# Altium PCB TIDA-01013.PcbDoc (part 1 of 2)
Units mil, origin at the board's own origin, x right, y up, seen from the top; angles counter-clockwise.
Board outline 2500 x 2300 mil, 4 copper layers (Top Layer, Layer 2 -GND, Layer 3 - PWR, Bottom Layer), stack 59.034 mil thick; 218 components, 101 nets, 532 pads, 275 vias.
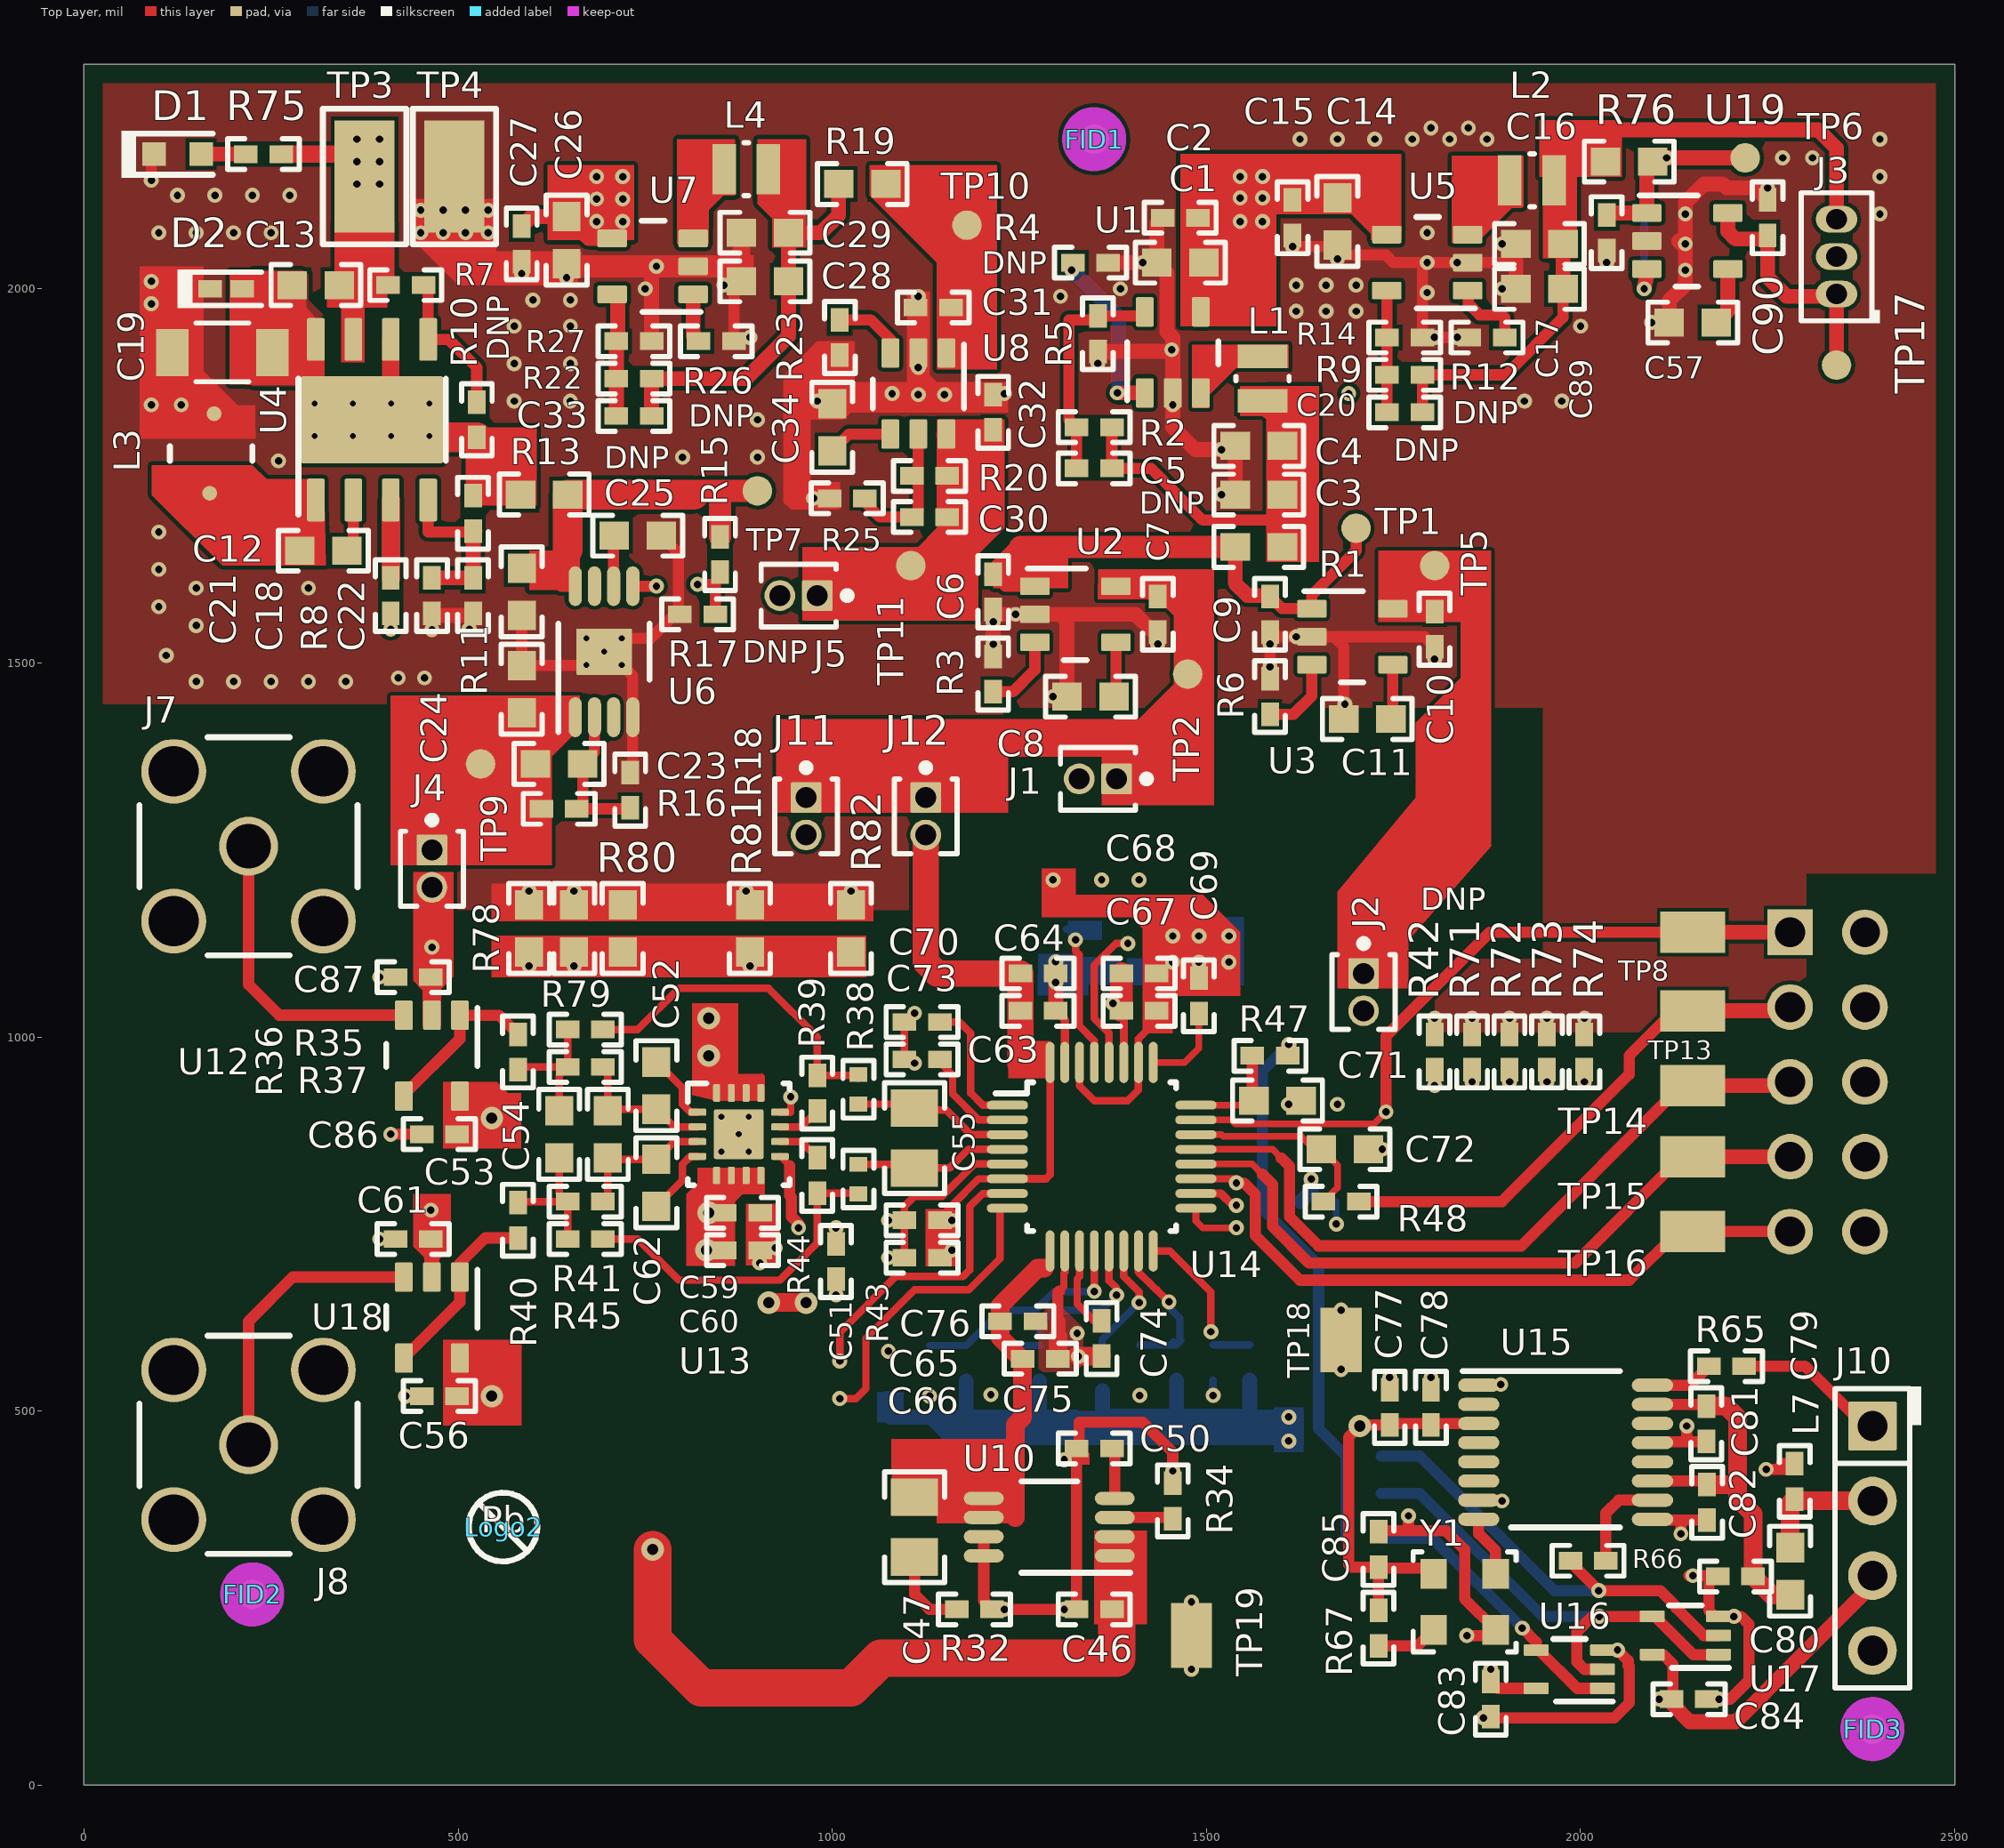
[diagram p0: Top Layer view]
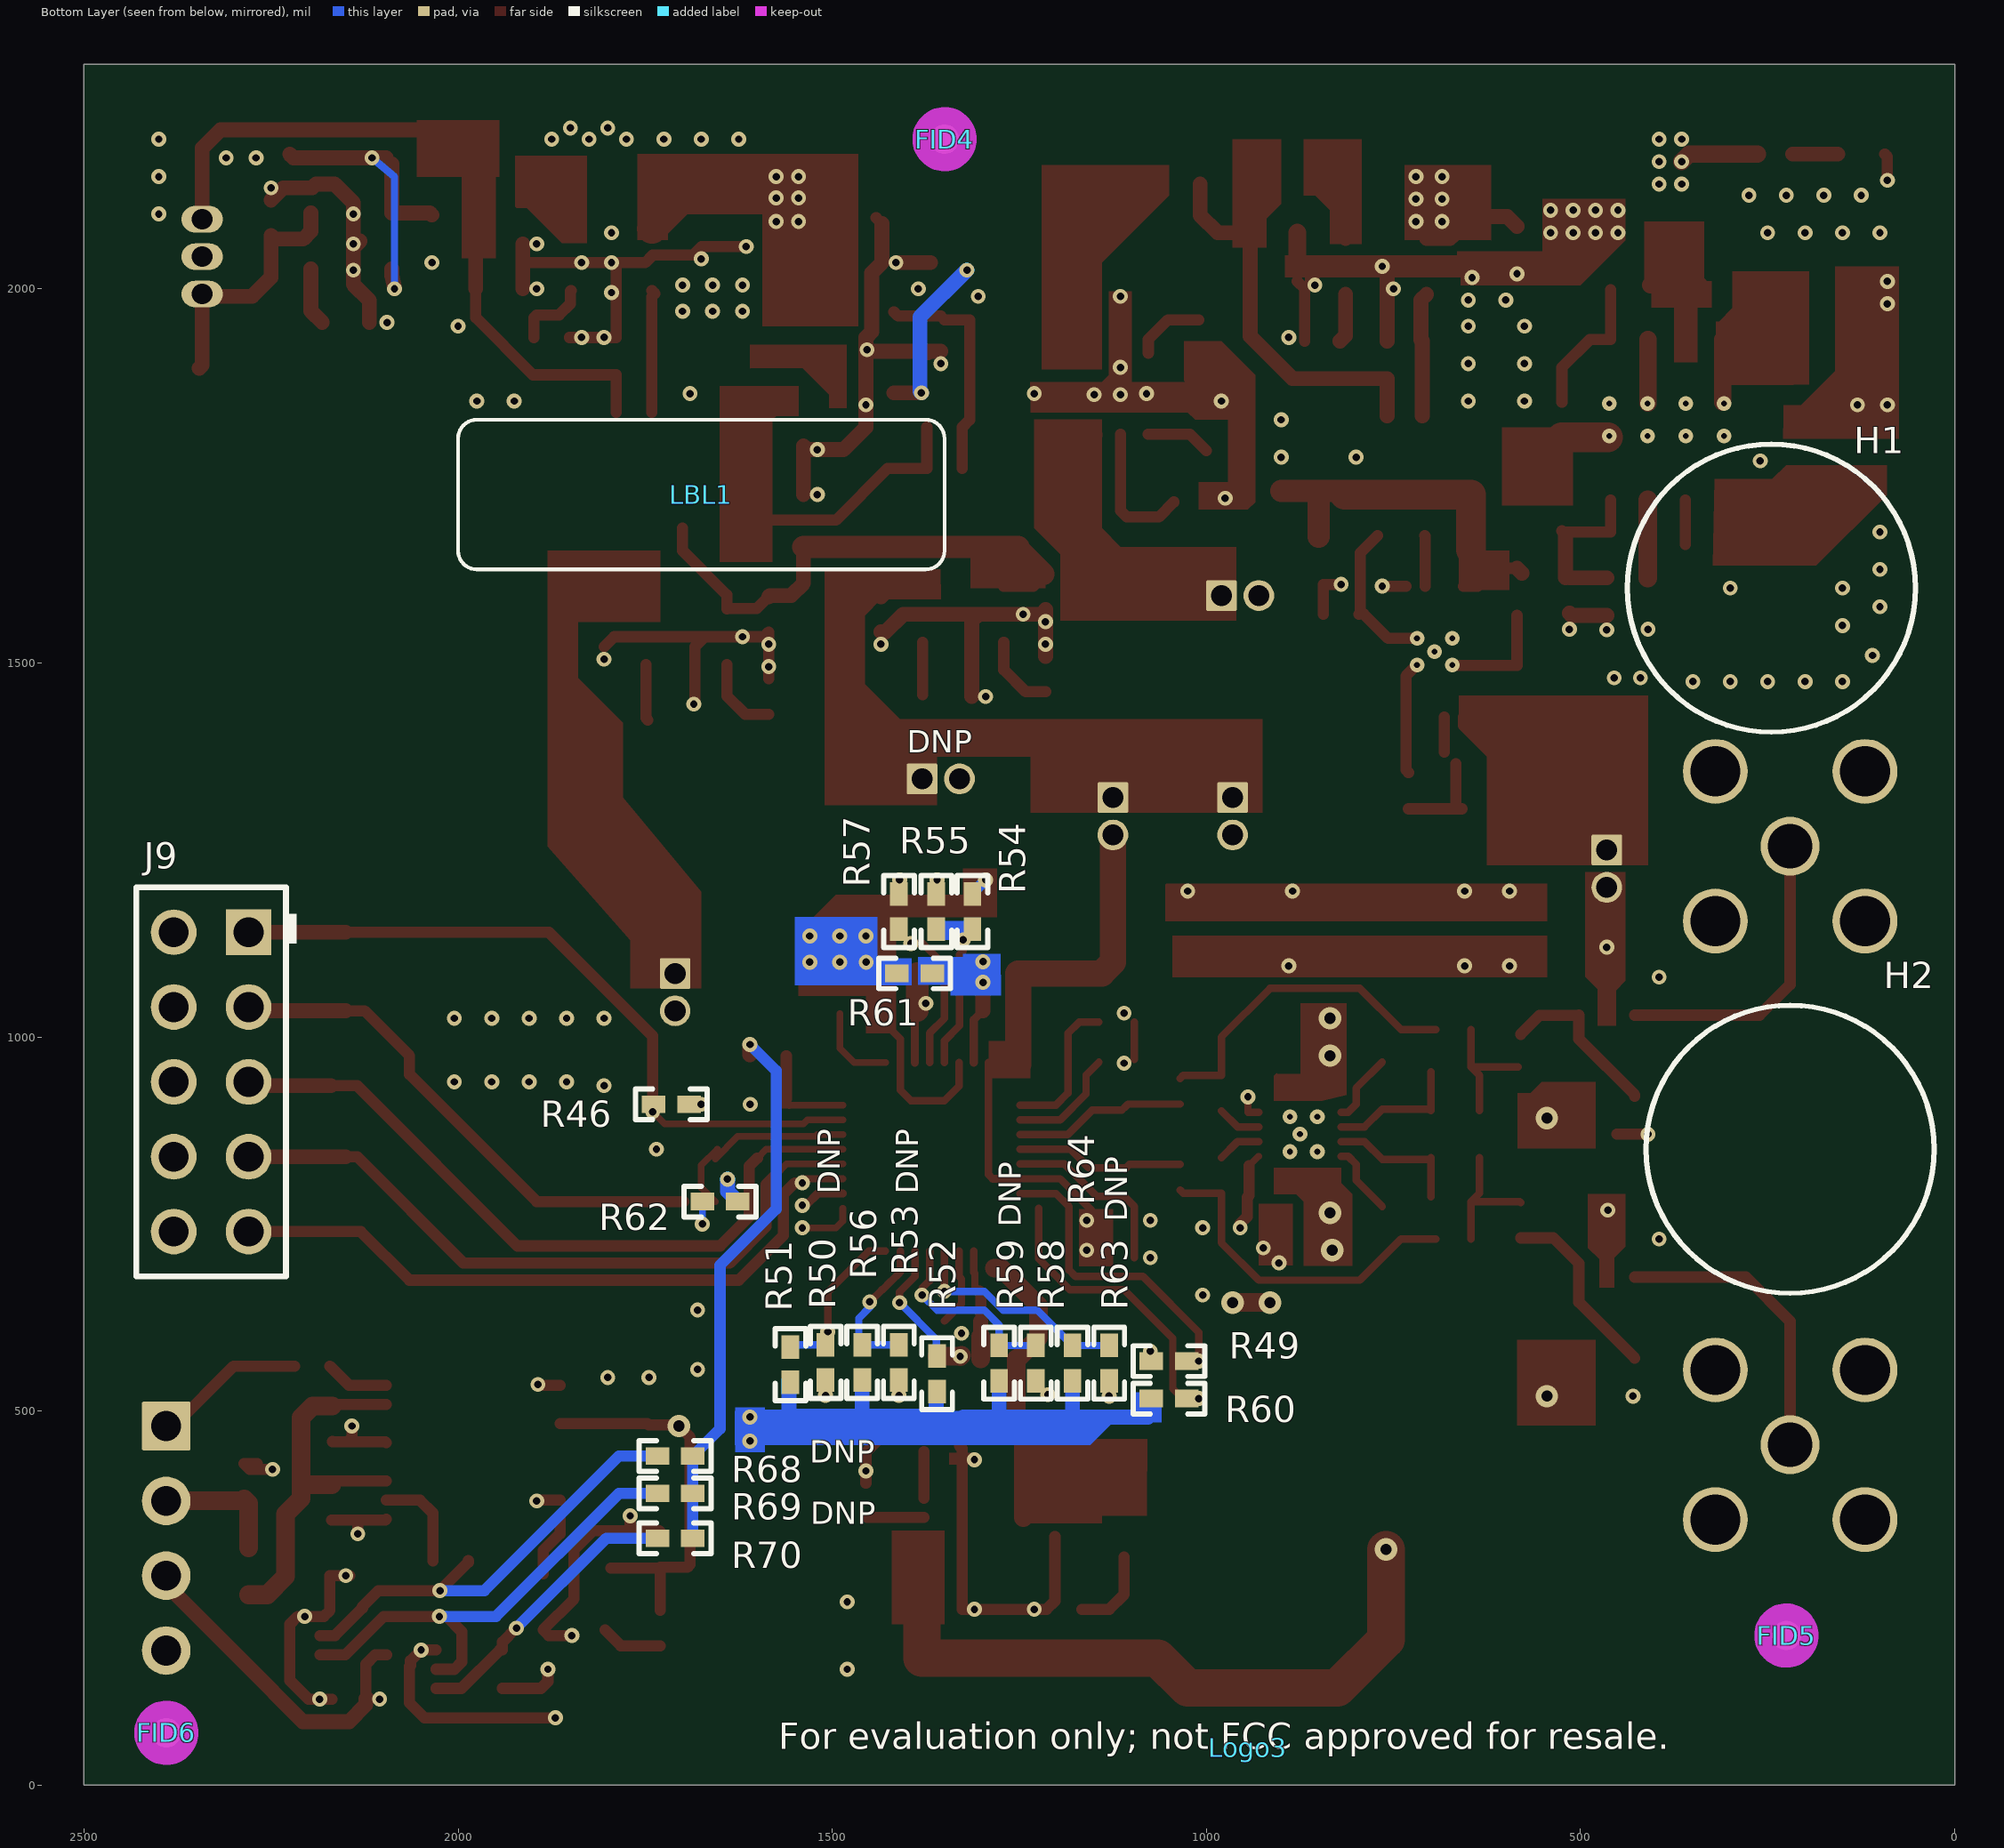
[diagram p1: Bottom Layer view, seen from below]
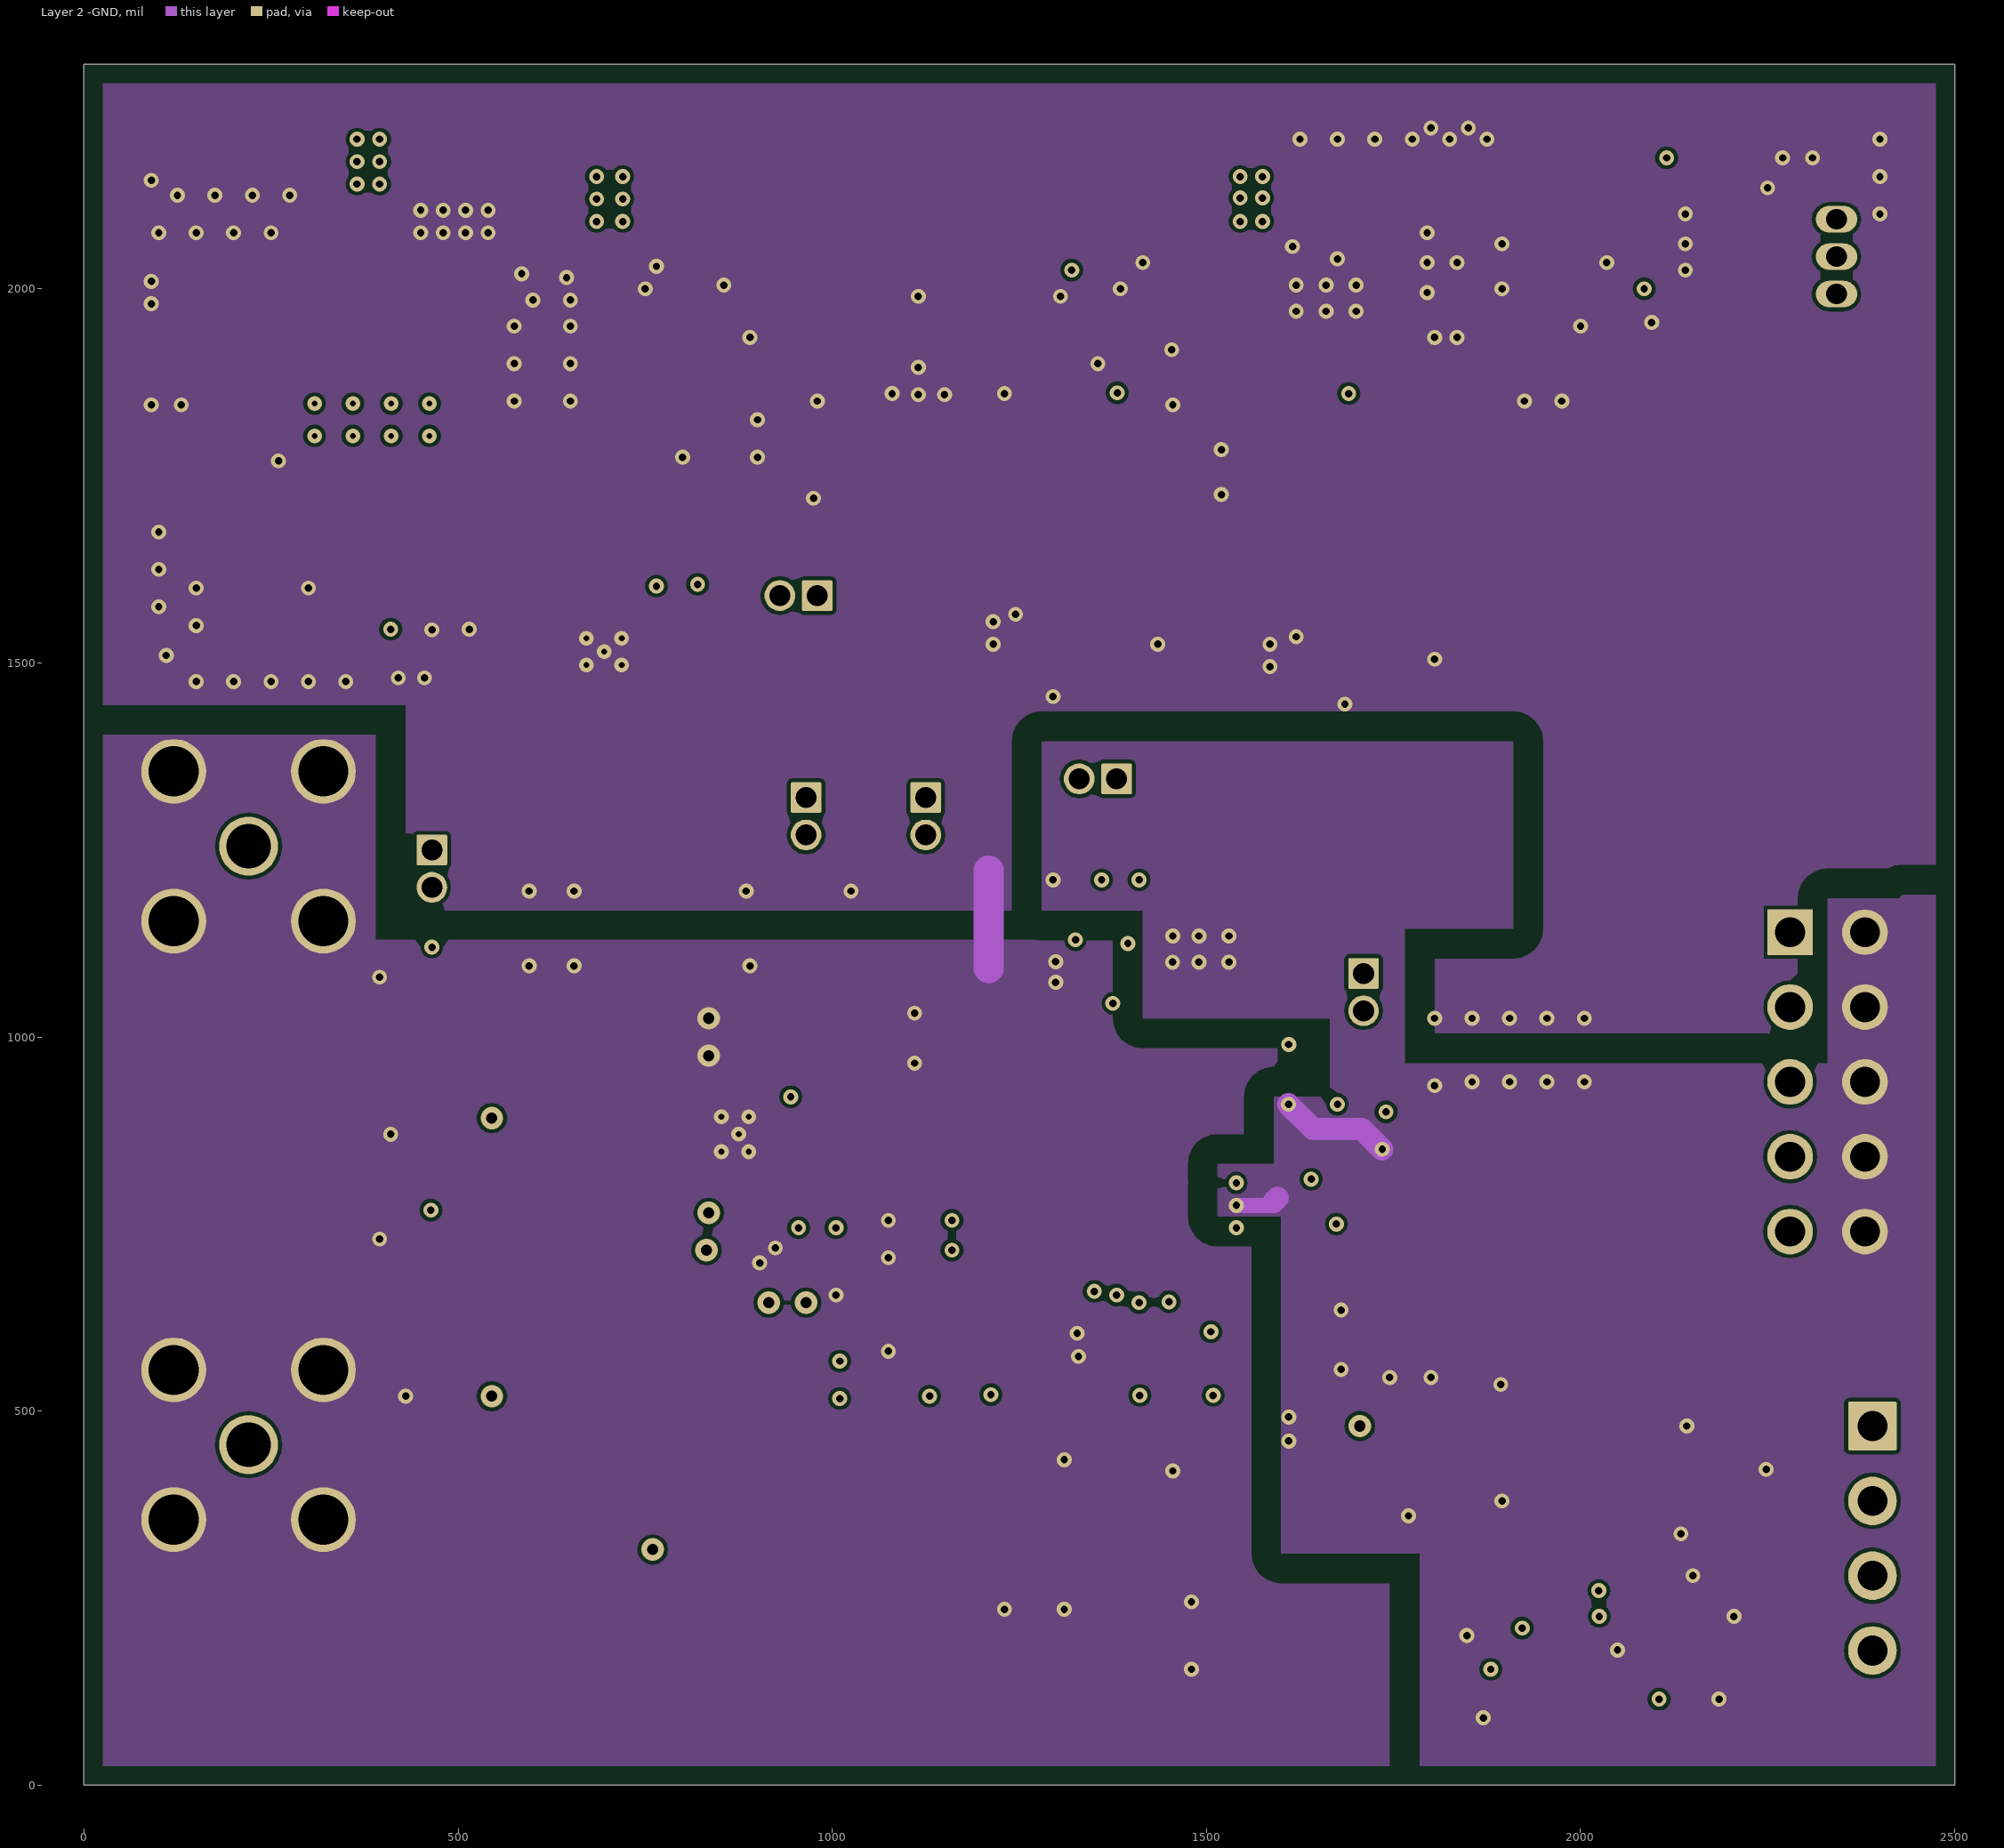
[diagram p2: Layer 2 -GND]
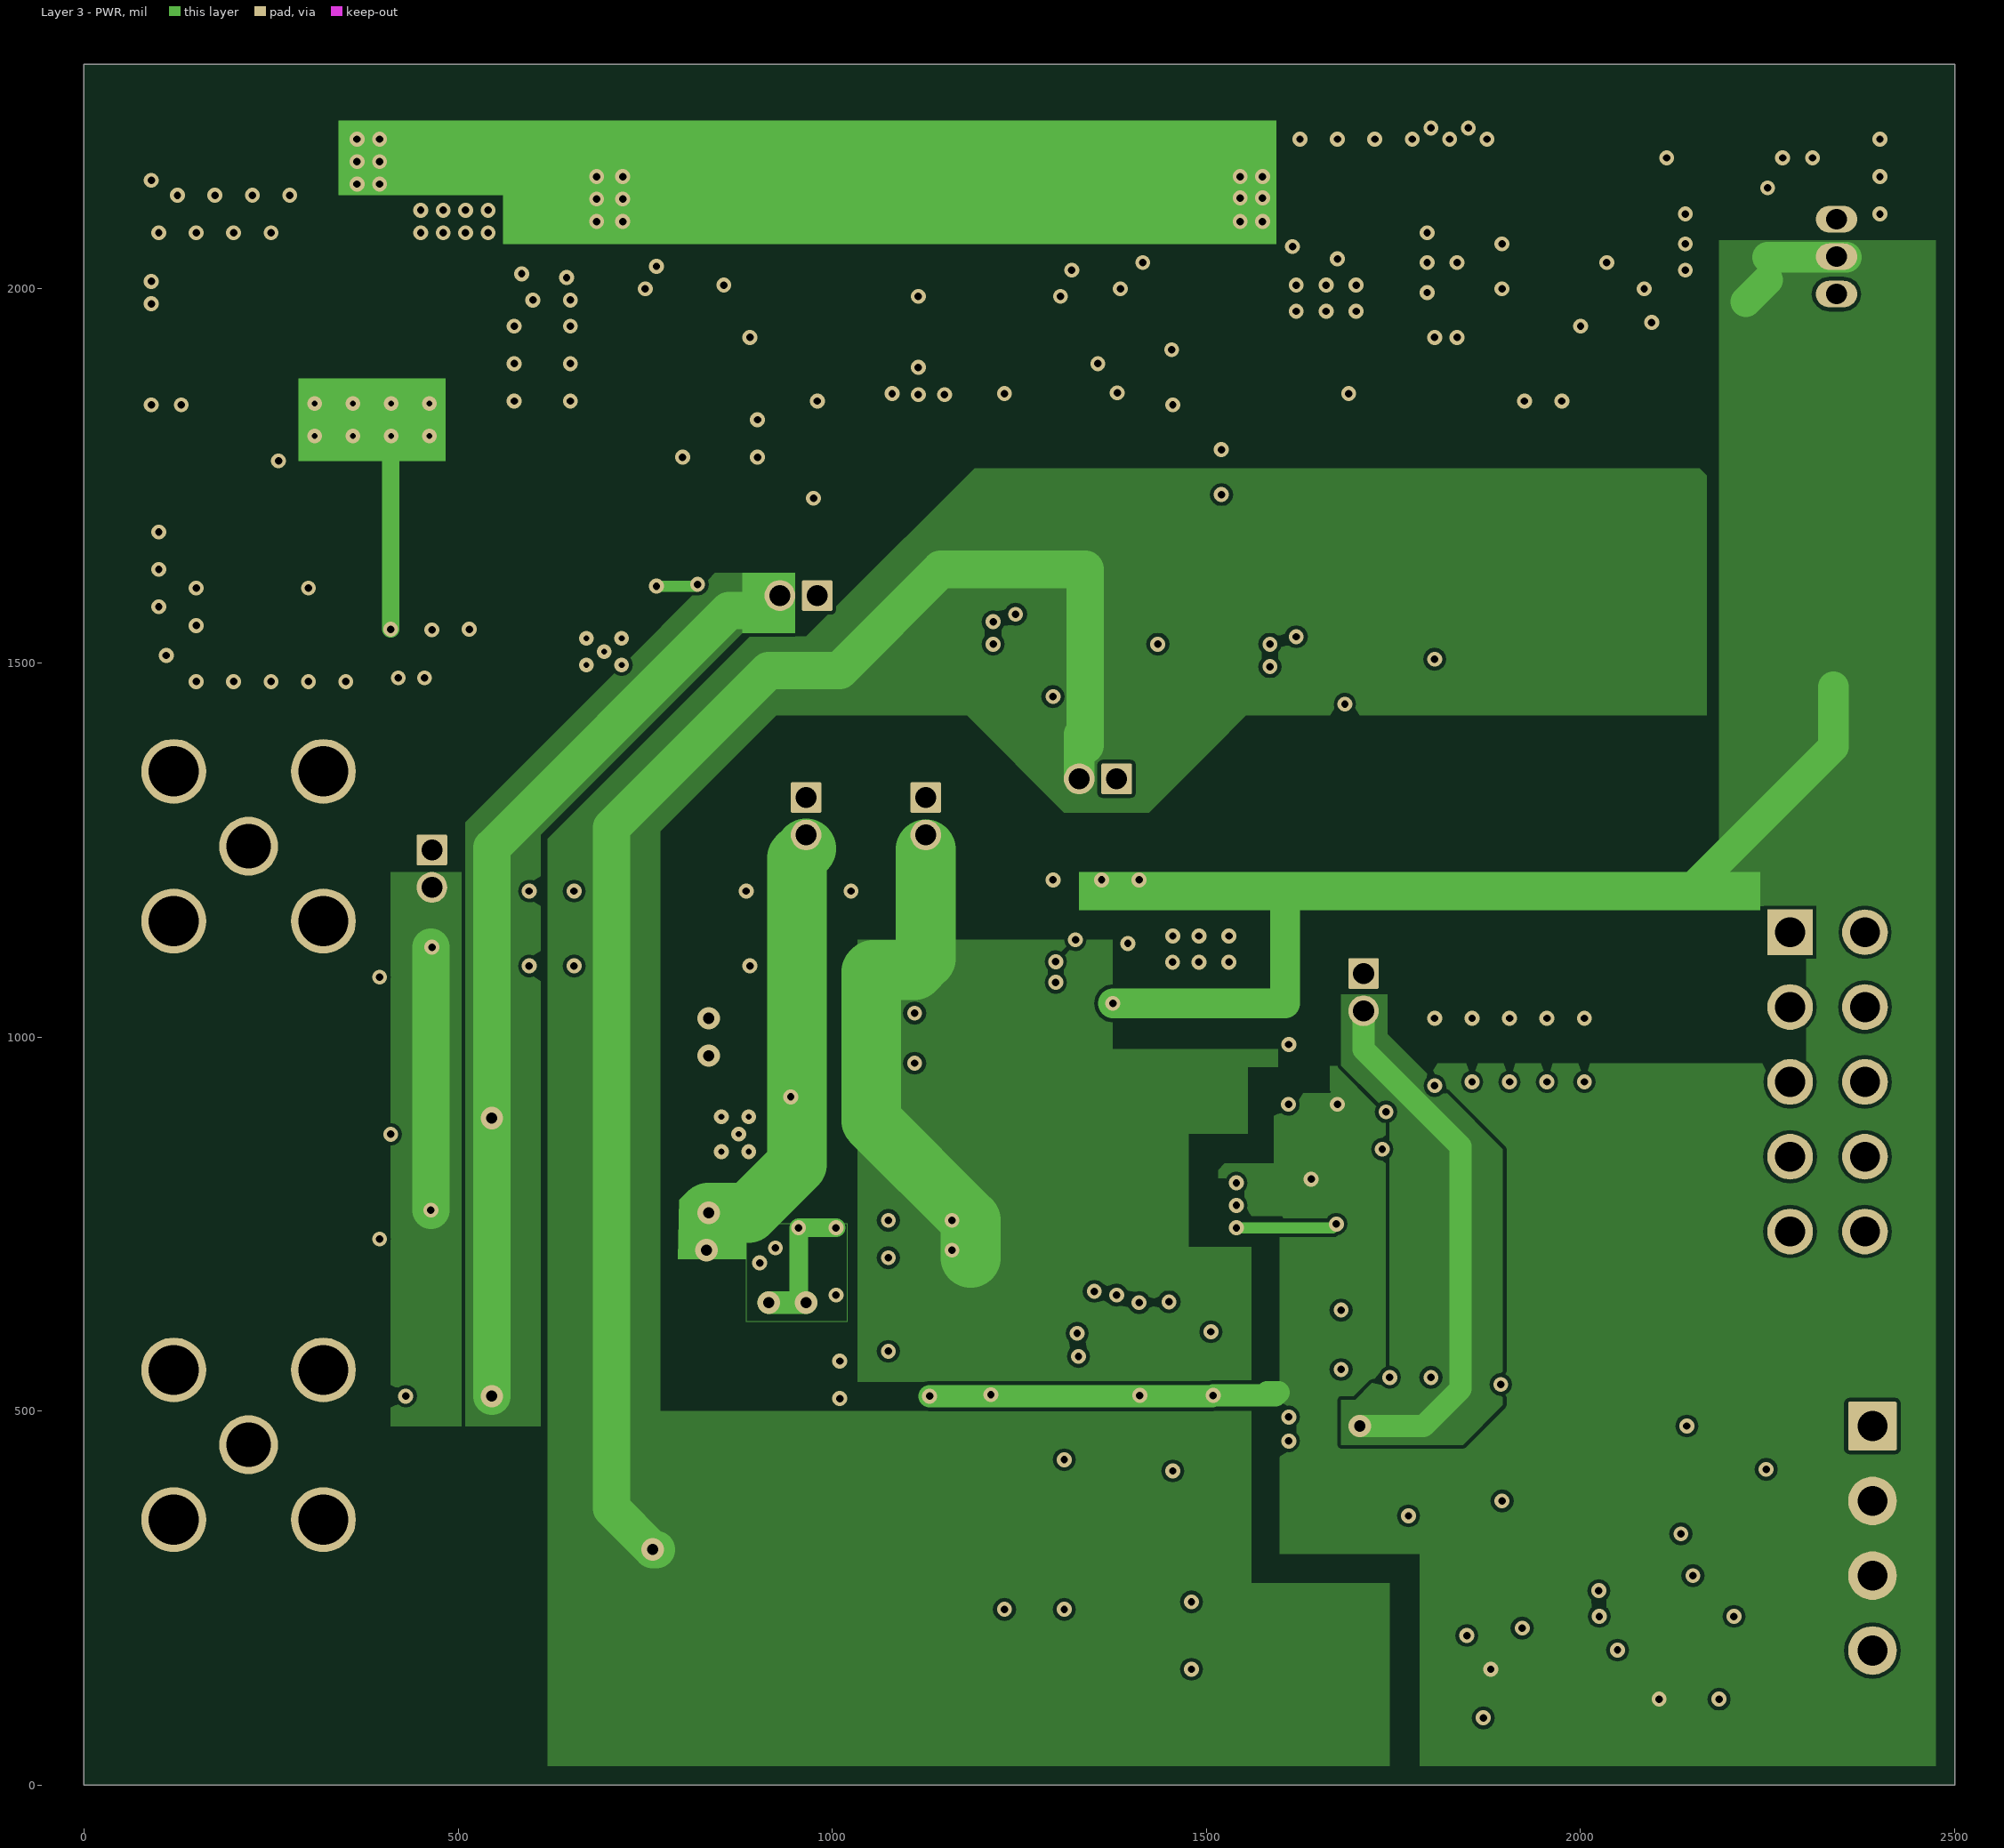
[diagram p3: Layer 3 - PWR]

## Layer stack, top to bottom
Top Solder: solder mask 0.4, Solder Resist, Dk 3.5
Top Layer: signal copper 1.4
Dielectric 1: prepreg 5.2, 370HR, Dk 4.2
Layer 2 -GND: signal copper 1.417
Dielectric 2: core 43, 370HR, Dk 4.2
Layer 3 - PWR: signal copper 1.417
Dielectric 3: prepreg 5.2, 370HR, Dk 4.2
Bottom Layer: signal copper 1.4
Bottom Solder: solder mask 0.4, Solder Resist, Dk 3.5

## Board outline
0,0 0,2300 2500,2300 2500,0

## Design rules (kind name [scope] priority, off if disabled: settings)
AcuteAngle [All] p1: minimum=4.50000000000000E+0001 checktracksonly=FALSE
AssemblyTestPointUsage [All] p1: valid=2
BoardOutlineClearance BoardOutlineClearance_MountingHoles [OnCopper and InComponentClass('Mounting Holes')] p1: gap=40
BoardOutlineClearance BoardOutlineClearance_Poly [OnCopper and IsPoly] p2: gap=25
BoardOutlineClearance [OnCopper and Not InComponentClass('Logo') and not InComponentClass('FiducialMark') and not InRegion(1000,500,4000,800) and not InPoly] p3: gap=75
Clearance Clearance_Keepouts [((IsTrack Or IsArc) And Not InPoly) And IsFree and IsKeepOut vs ((IsTrack Or IsArc) And Not InPoly) And IsFree and IsKeepOut] p1: gap=0
Clearance "Clearance_Poly_AGND TO DGND" [(InPolygon AND InNet('AGND')) vs (InPolygon AND InNet('DGND'))] p2: gap=40
Clearance Clearance_Poly [InPolygon] p3: gap=5
Clearance [All] p4: gap=7.87
ComponentClearance ComponentClearance_MountingHoles_FiducialMarks [InComponentClass('Mounting Holes') vs InComponentClass('FiducialMark')] p1: gap=50 collisioncheckmode=3 verticalgap=10 showdistances=FALSE
ComponentClearance ComponentClearance_Shunt [InComponentClass('Header') vs InComponentClass('Shunt')] p2: gap=0 collisioncheckmode=3 verticalgap=0 showdistances=FALSE
ComponentClearance ComponentClearance_Logo [InComponentClass('Logo')] p3: gap=10 collisioncheckmode=3 verticalgap=10 showdistances=FALSE
ComponentClearance ComponentClearance_ScrewToNut [(HasFootprint('NY PMS 440 0025 PH')) vs (HasFootprint('Keystone_1902C'))] p4: gap=5 collisioncheckmode=3 verticalgap=10 showdistances=FALSE
ComponentClearance ComponentClearance_MountingHoles [InComponentClass('Mounting Holes')] p5: gap=250 collisioncheckmode=3 verticalgap=100000 showdistances=FALSE
ComponentClearance ComponentClearance_SmallPassives [HasFootprint('0201*') or HasFootprint('0402*') or HasFootprint('0508') or HasFootprint('0603*') or HasFootprint('0612') or HasFootprint('0805*') or HasFootprint('0815*') or HasFootprint('0830*') or HasFootprint('1206*') or HasFootprint('1210*') or HasFootprint('1808*') or HasFootprint('1812*') or HasFootprint('1825*') or HasFootprint('2010*') or HasFootprint('2220*') or HasFootprint('2225*') or HasFootprint('2512*') or HasFootprint('2728*') or HasFootprint('3518*') vs HasFootprint('0201*') or HasFootprint('0402*') or HasFootprint('0508') or HasFootprint('0603*') or HasFootprint('0612') or HasFootprint('0805*') or HasFootprint('0815*') or HasFootprint('0830*') or HasFootprint('1206*') or HasFootprint('1210*') or HasFootprint('1808*') or HasFootprint('1812*') or HasFootprint('1825*') or HasFootprint('2010*') or HasFootprint('2220*') or HasFootprint('2225*') or HasFootprint('2512*') or HasFootprint('2728*') or HasFootprint('3518*')] p6: gap=14.96 collisioncheckmode=3 verticalgap=10 showdistances=FALSE
ComponentClearance ComponentClearance_THtoSMT [IsThruComponent vs IsSMTComponent] p7: gap=10 collisioncheckmode=3 verticalgap=30 showdistances=FALSE
ComponentClearance ComponentClearance_THtoTH [IsThruComponent vs IsThruComponent] p8: gap=30 collisioncheckmode=3 verticalgap=30 showdistances=FALSE
ComponentClearance [All] p9: gap=30 collisioncheckmode=3 verticalgap=10 showdistances=FALSE
DiffPairsRouting [All] p1: maxlimit=100 minlimit=10 mostfreqgap=10 toplayer_minwidth=15 toplayer_maxwidth=15 toplayer_prefwidth=15 midlayer1_minwidth=15 midlayer1_maxwidth=15 midlayer1_prefwidth=15 midlayer2_minwidth=15 midlayer2_maxwidth=15 midlayer2_prefwidth=15 bottomlayer_minwidth=15 bottomlayer_maxwidth=15 bottomlayer_prefwidth=15 maxuncoupledlength=1000
FabricationTestPointUsage TestPointUsage [All] p1: valid=2 allowmultiple=FALSE
FabricationTestpoint Testpoint [All] p1: side=3 testpointundercomponent=TRUE minsize=40 maxsize=100 preferedsize=60 minholesize=0 maxholesize=40 preferedholesize=32 testpointgrid=1 allowsidetop=TRUE allowsidebottom=TRUE usegrid=TRUE gridtolerance=0.01
FanoutControl Fanout_LCC [IsLCC] p1: bgadir=Out bgaviamode=Centered fanoutstyle=Auto fanoutdirection=Alternating viagrid=1 // Fanout_LCC (Default Rule)
FanoutControl Fanout_BGA [IsBGA] p2: bgadir=Out bgaviamode=Centered fanoutstyle=Auto fanoutdirection=Alternating viagrid=1 // Fanout_BGA (Default Rule)
FanoutControl Fanout_Default [All] p4: bgadir=Out bgaviamode=Centered fanoutstyle=Auto fanoutdirection=Alternating viagrid=1 // Fanout_Default (Default Rule)
FanoutControl Fanout_Small [(CompPinCount < 5)] p5: bgadir=Out bgaviamode=Centered fanoutstyle=Auto fanoutdirection=OutThenIn viagrid=1 // Fanout_Small (Default Rule)
HoleSize [All] p1: absolutevalues=TRUE maxlimit=251 minlimit=7.87 maxpercent=80.000 minpercent=20.000
MinimumAnnularRing MinimumAnnularRing_ThermalPadVias [IsVia and InAnyComponent] p1: minimumring=5.91
MinimumAnnularRing [All] p2: minimumring=3.5
MinimumSolderMaskSliver MinimumSolderMaskSliver_Logo [InComponentClass('Logo') vs InComponentClass('Logo')] p1: minsoldermaskwidth=0.7
MinimumSolderMaskSliver [All] p2: minsoldermaskwidth=3
PlaneConnect [All] p1: planeconnectstyle=Direct reliefexpansion=10 reliefentries=4 reliefconductorwidth=10 reliefairgap=10
PolygonConnect [All] p1: connectstyle=Direct reliefconductorwidth=10 reliefentries=4 polygonreliefangle="90 Angle" airgapwidth=10
RoutingVias ThermalPadVias [IsVia and InAnyComponent] p1: holewidth=7.87 width=19.68 viastyle="Through Hole" minholewidth=7.87 minwidth=19.68 maxholewidth=12.99 maxwidth=23.62
RoutingVias [All] p2: holewidth=16 width=34 viastyle="Through Hole" minholewidth=7.87 minwidth=20 maxholewidth=40 maxwidth=65
SilkToBoardRegionClearance [Not ((IsComment or IsDesignator) And (Hide <> 'False')) and not InRegion(1000,500,4000,800)] p1:
SilkToSilkClearance SilkToSilkClearance_Pb-FreeLogo [(HasFootprint('Pb-Free_Overlay_Medium') OR HasFootprint('Pb-Free_Overlay_Small')) vs (HasFootprint('Pb-Free_Overlay_Medium') OR HasFootprint('Pb-Free_Overlay_Small'))] p1: silktosilkclearance=0
SilkToSilkClearance [All] p2: silktosilkclearance=2
SilkToSolderMaskClearance SilkToComponentPadClearance [(IsPad or IsFill or IsRegion) and InAnycomponent] p1: minsilkscreentomaskgap=2 clearancetoexposedcopper=TRUE
SilkToSolderMaskClearance "Silk to Solder Mask Opening" [All] p2: minsilkscreentomaskgap=1 clearancetoexposedcopper=FALSE
SolderMaskExpansion [All] p1: expansion=1.97
Width [All] p1: maxlimit=100 minlimit=6 preferedwidth=10 checkconnectedcopper=TRUE
15 further rules are at their usual default settings.

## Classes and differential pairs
component class TIDA-01013_EVM_Hardware: !PCB FID1 FID2 FID3 FID4 FID5 FID6 LBL1 Logo2 Logo3 ZZ1 ZZ2 ZZ3 ZZ4
component class Label: LBL1
component class FiducialMark: FID1 FID2 FID3 FID4 FID5 FID6
component class AssemblyNote: ZZ1 ZZ2 ZZ3 ZZ4
component class Header: J1 J2 J3 J4 J5 J10 J11 J12 J?
component class LP_Front_End_ADC: C63 C64 C65 C66 "C66 DNP" C67 C68 C69 C70 C71 C72 C73 C74 C75 C76 J9 R42 R46 R47 R48 R49 R50 R51 R52 R53 R54 R55 R56 R57 R58 R59 R60 R61 R62 R63 R64 R71 R72 R73 R74 TP8 TP13 TP14 TP15 TP16 TP18 TP19 U14
component class LP_Front_End_AFE: 30 C46 C47 C50 C51 C52 C53 C54 C55 C56 C59 C60 C61 C62 C86 C87 J7 J8 R32 R34 R35 R36 R37 R38 R39 R40 R41 R43 R44 R45 U10 U12 U13 U18
component class LP_Front_End_ClockTree: C77 C78 C79 C80 C81 C82 C83 C84 C85 J10 L7 R65 R66 R67 R68 R69 R70 U15 U16 U17 Y1
component class LP_Front_End_PWR: C1 C2 C3 C4 C5 C6 C7 C8 C9 C10 C11 C12 C13 C14 C15 C16 C17 C18 C19 C20 C21 C22 C23 C24 C25 C26 C27 C28 C29 C30 C31 C32 C33 C34 C57 C89 C90 D1 D2 H1 H2 J1 J2 J3 J4 J5 J11 J12 J? L1 L2 L3 L4 R1 R2 R3 R4 R5 R6 R7 R8 R9 R10 R11 R12 R13 R14 R15 R16 R17 R18 R19 R20 R22 R23 R25 R26 R27 R75 R76 R78 R79 R80 R81 R82 TP1 TP2 TP3 TP4 TP5 TP6 TP7 TP9 TP10 TP11 TP17 U1 U2 U3 U4 U5 U6 U7 U8 U19

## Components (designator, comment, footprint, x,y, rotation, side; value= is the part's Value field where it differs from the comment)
C1 "C1608X5R1E106M080AC" 0603 1465,2035 r180 top
C2 "GRM155R61E104KA87D" 0402 1465,2095 r180 top
C3 "C1608X5R1E106M080AC" 0603 1570,1725 r180 top
C4 "C1608X5R1E106M080AC" 0603 1570,1790 r180 top
C5 "DNP" 0402 1350,1760 r180 top
C6 "GRM155R61E104KA87D" 0402 1215,1595 r270 top
C7 "GRM155R61E105KA12D" 0402 1435,1565 r270 top
C8 "GRM188R61H103KA01D" 0603 1345,1455 r180 top
C9 "GRM155R61E104KA87D" 0402 1585,1565 r270 top
C10 "GRM155R61E105KA12D" 0402 1805,1545 r270 top
C11 "GRM188R61H103KA01D" 0603 1715,1425 r180 top
C12 "GRM188R61E474KA12D" 0603 320,1650 r180 top
C13 "C1608X5R1E106M080AC" 0603 310,2005 r180 top
C14 "C1608X5R1E106M080AC" 0603 1675,2090 r270 top
C15 "GRM155R61E104KA87D" 0402 1615,2095 r270 top
C16 "C1608X5R1E106M080AC" 0603 1945,2060 r180 top
C17 "C1608X5R1E106M080AC" 0603 1945,2000 r180 top
C18 "GRM1555C1H910JA01D" 0402 465,1590 r90 top
C19 "C3216X5R1A686M160AC" 1206_190 185,1915 r0 top
C20 "DNP" 0402 1765,1835 r180 top
C21 "C1005X5R1E225K050BC" 0402 410,1590 r270 top
C22 "C1608X5R1E106M080AC" 0603 585,1595 r270 top
C23 "GRM188R61H103KA01D" 0603 635,1365 r0 top
C24 "C1608X5R1E106M080AC" 0603 585,1465 r90 top
C25 "GRM188R61H103KA01D" 0603 740,1670 r0 top
C26 "C1608X5R1E106M080AC" 0603 645,2065 r270 top
C27 "GRM155R61E104KA87D" 0402 585,2060 r270 top
C28 "C1608X5R1E106M080AC" 0603 910,2010 r180 top
C29 "C1608X5R1E106M080AC" 0603 910,2075 r180 top
C30 "GRM1555C1H130JA01D" 0402 1130,1695 r180 top
C31 "GRM155R61E104KA87D" 0402 1135,1975 r180 top
C32 "GRM155R61E105KA12D" 0402 1215,1835 r90 top
C33 "DNP" 0402 735,1830 r180 top
C34 "GRM188R61H103KA01D" 0603 1000,1815 r90 top
C46 "CL05A106MP5NUNC" 0402 1350,235 r180 top
C47 "GRM21BR61A476ME15" 0805_HV 1110,345 r270 top
C50 "GRM155R61A105KE15D" 0402 1350,450 r180 top
C51 "C1005X5R1A224K050BC" 0402 1005,700 r270 top
C52 "GRM1885C2A271JA01D" 0603 765,935 r270 top
C53 "C1608C0G2A471J" 0603 635,870 r270 top
C54 "C1608C0G2A102J080AA" 0603 700,870 r270 top
C55 "GRM2165C2A162JA01D" 0805_HV 1110,865 r270 top
C56 "C1005X5R1A104K050BA" 0402 475,520 r0 top
C57 "GRM188R61H103KA01D" 0603 2150,1955 r180 top
C59 "C1005X5R1A104K050BA" 0402 880,765 r0 top
C60 "CL05A106MP5NUNC" 0402 880,715 r180 top
C61 "C1005X5R1A104K050BA" 0402 440,730 r0 top
C62 "GRM1885C2A271JA01D" 0603 765,805 r90 top
C63 "C1005X5R1A104K050BA" 0402 1275,1035 r180 top
C64 "CL05A106MP5NUNC" 0402 1275,1085 r0 top
C65 "C1005X5R1A104K050BA" 0402 1120,755 r0 top
C66 "CL05A106MP5NUNC" 0402 1120,705 r180 top
C67 "C1005X5R1A104K050BA" 0402 1410,1035 r180 top
C68 "CL05A106MP5NUNC" 0402 1410,1085 r0 top
C69 "GRM155R61A105KE15D" 0402 1490,1055 r90 top
C70 "GRM155R61A105KE15D" 0402 1120,1020 r0 top
C71 "06035A100JAT2A" 0603 1595,915 r0 top
C72 "GRM1885C2A100JA01D" 0603 1685,850 r0 top
C73 "GRM155R61A105KE15D" 0402 1120,970 r180 top
C74 "GRM155R61A105KE15D" 0402 1360,597 r270 top
C75 "GRM155R61A105KE15D" 0402 1278,570 r0 top
C76 "C1005X5R1A104K050BA" 0402 1248,620 r180 top
C77 "CL05A106MP5NUNC" 0402 1745,505 r90 top
C78 "C1005X5R1A104K050BA" 0402 1800,505 r270 top
C79 "CL05A106MP5NUNC" 0402 2286,406 r90 top
C80 "GRM155R61A105KE15D" 0402 2207,279 r180 top
C81 "C1005X5R1A104K050BA" 0402 2168,483 r90 top
C82 "C1005X5R1A104K050BA" 0402 2169,378 r90 top
C83 "C1005X5R1A104K050BA" 0402 1880,115 r270 top
C84 "C1005X5R1A104K050BA" 0402 2145,115 r0 top
C85 "C1005X5R1A104K050BA" 0402 1730,315 r270 top
C86 "C1005X5R1A104K050BA" 0402 475,870 r0 top
C87 "C1005X5R1A104K050BA" 0402 440,1080 r0 top
C89 "GRM155R61E104KA87D" 0402 2035,2075 r270 top
C90 "GRM155R61E105KA12D" 0402 2250,2095 r90 top
D1 "150060RS75000" WL-SMCW_RED 125,2180 r0 top
D2 "BAT41KFILM" SOD-523 190,2000 r0 top
FID1 "Fiducial" Fiducial10-20 1350,2200 r0 top
FID2 "Fiducial" Fiducial10-20 225,255 r0 top
FID3 "Fiducial" Fiducial10-20 2390,75 r0 top
FID4 "Fiducial" Fiducial10-20 1350,2200 r180 bottom
FID5 "Fiducial" Fiducial10-20 225,200 r180 bottom
FID6 "Fiducial" Fiducial10-20 2390,70 r180 bottom
H1 "SJ61A2" Bumpon_SJ61A2 245,1600 r90 bottom
H2 "SJ61A2" Bumpon_SJ61A2 220,850 r180 bottom
J1 "GRPB021VWVN-RC" Sullins_GRPB021VWVN-RC 1355,1345 r180 top
J2 "GRPB021VWVN-RC" Sullins_GRPB021VWVN-RC 1710,1060 r270 top
J3 "GRPB031VWVN-RC" Sullins_GRPB031VWVN-RC 2342,2043 r90 top
J4 "GRPB021VWVN-RC" Sullins_GRPB021VWVN-RC 465,1225 r270 top
J5 "GRPB021VWVN-RC" Sullins_GRPB021VWVN-RC 955,1590 r180 top
J7 "AINN" Amphenol_901-144-8RFX 220,1255 r0 top
J8 "AINP" Amphenol_901-144-8RFX 220,455 r0 top
J9 "PPTC052LFBN-RC" Sullins_xPxC052LFBN 2330,940 r270 bottom
J10 "TSW-104-07-G-S" TSW-104-07-G-S 2390,330 r270 top
J11 "GRPB021VWVN-RC" Sullins_GRPB021VWVN-RC 965,1295 r270 top
J12 "GRPB021VWVN-RC" Sullins_GRPB021VWVN-RC 1125,1295 r270 top
L1 "SRN2010TA-100M" SRN2010TA 1575,1880 r270 top
L2 "SRN2010TA-100M" SRN2010TA 1935,2145 r0 top
L3 "SRU2016-220Y" SRU2016 170,1780 r90 top
L4 "SRN2010TA-100M" SRN2010TA 885,2160 r0 top
L7 "HZ0603C601R-10" 0603 2280,286 r270 top
LBL1 "Size: 0.65\" x 0.20 \"" Label_650x200 1675,1725 r180 bottom
Logo2 "Pb-Free Symbol" Pb-Free_Overlay_Small 560,345 r0 top
Logo3 "FCC disclaimer" FCC_disclaimer 945,50 r180 bottom
R1 "CRCW06030000Z0EA" 0603 1570,1655 r180 top
R2 "CRCW0402100KFKED" 0402 1350,1815 r0 top
R3 "" 0402 1215,1485 r90 top
R4 "DNP" 0402 1345,2035 r0 top
R5 "CRCW040230K9FKED" 0402 1355,1940 r90 top
R6 "" 0402 1585,1455 r90 top
R7 "" 0402 430,2005 r0 top
R8 "CRCW040275K0FKED" 0402 520,1590 r270 top
R9 "CRCW0402105KFKED" 0402 1765,1885 r0 top
R10 "DNP" 0402 525,1825 r90 top
R11 "CRCW040217K4FKED" 0402 520,1700 r270 top
R12 "DNP" 0402 1875,1935 r180 top
R13 "CRCW06030000Z0EA" 0603 615,1725 r0 top
R14 "CRCW040239K2FKED" 0402 1765,1935 r180 top
R15 "" 0402 850,1645 r270 top
R16 "CRCW040236K0JNED" 0402 635,1305 r180 top
R17 "DNP" 0402 820,1565 r0 top
R18 "CRCW040210K5FKED" 0402 730,1330 r270 top
R19 "CRCW06030000Z0EA" 0603 1040,2140 r0 top
R20 "ERJ-2RKF9762X" 0402 1130,1750 r0 top
R22 "RC0402FR-07100KL" 0402 735,1880 r0 top
R23 "" 0402 1010,1935 r270 top
R25 "RC0402FR-0730K1L" 0402 1020,1720 r0 top
R26 "DNP" 0402 845,1930 r0 top
R27 "CRCW040217K8FKED" 0402 735,1930 r180 top
R32 "ERJ-2BQFR22X" 0402 1190,235 r180 top
R34 "CRCW0402120KFKED" 0402 1455,380 r270 top
R35 "ERA-2AEB102X" 0402 670,1010 r0 top
R36 "CRCW04023K40FKED" 0402 580,980 r270 top
R37 "ERJ-2RKF3300X" 0402 670,960 r0 top
R38 "CPF0402B10RE1" CPF0402 1035,930 r270 top
R39 "CRCW04024R99FKED" 0402 980,925 r90 top
R40 "CRCW04023K40FKED" 0402 580,755 r90 top
R41 "ERJ-2RKF3300X" 0402 670,780 r0 top
R42 "DNP" 0402 1805,980 r90 top
R43 "CPF0402B10RE1" CPF0402 1035,810 r90 top
R44 "CRCW04024R99FKED" 0402 980,815 r270 top
R45 "ERA-2AEB102X" 0402 670,730 r0 top
R46 "RMCF0402FT100K" 0402 1715,910 r0 bottom
R47 "CRCW040210R0FKED" 0402 1585,975 r0 top
R48 "CRCW04020000Z0ED" 0402 1680,780 r0 top
R49 "CRCW0402120KFKED" 0402 1050,566.79 r180 bottom
R50 "DNP" 0402 1509,565 r270 bottom
R51 "CRCW04020000Z0ED" 0402 1556,562 r90 bottom
R52 "CRCW04020000Z0ED" 0402 1360,550 r270 bottom
R53 "DNP" 0402 1411,565 r270 bottom
R54 "CRCW04020000Z0ED" 0402 1312.78,1167.66 r270 bottom
R55 "DNP" 0402 1360.96,1167.66 r90 bottom
R56 "CRCW04020000Z0ED" 0402 1460,565 r90 bottom
R57 "CRCW0402100KFKED" 0402 1410.96,1167.66 r90 bottom
R58 "CRCW04020000Z0ED" 0402 1228,564 r270 bottom
R59 "DNP" 0402 1277,564 r90 bottom
R60 "RK73H1ETTP1002F" 0402 1050,516.79 r0 bottom
R61 "DNP" 0402 1390,1085 r180 bottom
R62 "RMCF0402FT100K" 0402 1650,780 r180 bottom
R63 "DNP" 0402 1130,564 r270 bottom
R64 "CRCW04020000Z0ED" 0402 1179,564 r90 bottom
R65 "CRCW040243R2FKED" 0402 2195,560 r0 top
R66 "CRCW040243R2FKED" 0402 2010,300 r180 top
R67 "RMCF0402FT100K" 0402 1730,210 r90 top
R68 "DNP" 0402 1710,440 r0 bottom
R69 "DNP" 0402 1710,390 r0 bottom
R70 "" 0402 1710,330 r0 bottom
R71 "DNP" 0402 1855,980 r90 top
R72 "DNP" 0402 1905,980 r90 top
R73 "DNP" 0402 1955,980 r90 top
R74 "DNP" 0402 2005,980 r90 top
R75 "PCF0402-03-49K9BT1" 0402 240,2180 r0 top
R76 "CRCW06030000Z0EA" 0603 2065,2170 r0 top
R78 "DNP" 0603 595,1145 r90 top
R79 "DNP" 0603 655,1145 r90 top
R80 "DNP" 0603 720,1145 r90 top
R81 "DNP" 0603 890,1145 r90 top
R82 "DNP" 0603 1025,1145 r90 top
TP1 "TESTPOINT" TP_SM_1MM 1700,1680 r0 top
TP2 "TESTPOINT" TP_SM_1MM 1475,1485 r90 top
TP3 "TESTPOINT" Keystone_5019 375,2150 r90 top
TP4 "TESTPOINT" Keystone_5019 495,2150 r90 top
TP5 "TESTPOINT" TP_SM_1MM 1805,1630 r180 top
TP6 "TESTPOINT" TP_SM_1MM 2220,2175 r0 top
TP7 "TESTPOINT" TP_SM_1MM 900,1730 r0 top
TP8 "TESTPOINT" Harwin_S2751-46R 2150,1140 r180 top
TP9 "TESTPOINT" TP_SM_1MM 530,1365 r0 top
TP10 "TESTPOINT" TP_SM_1MM 1180,2085 r180 top
TP11 "TESTPOINT" TP_SM_1MM 1105,1630 r0 top
TP13 "TESTPOINT" Harwin_S2751-46R 2150,1035 r0 top
TP14 "TESTPOINT" Harwin_S2751-46R 2150,935 r0 top
TP15 "TESTPOINT" Harwin_S2751-46R 2150,840 r0 top
TP16 "TESTPOINT" Harwin_S2751-46R 2150,740 r180 top
TP17 "TESTPOINT" TP_SM_1MM 2342,1898 r90 top
TP18 "TESTPOINT" Harwin_S2751-46R 1680,595 r90 top
TP19 "TESTPOINT" Harwin_S2751-46R 1480,200 r90 top
U1 "TPS560200DBVR" DBV0005A_N 1455,1915 r90 top
U2 "TPS79133DBVR" DBV0005A_N 1325,1565 r0 top
U3 "TPS79133DBVR" DBV0005A_N 1695,1535 r0 top
U4 "LMR23610ADDAR" DDA0008E_N 385,1825 r90 top
U5 "TPS560200DBVR" DBV0005A_N 1795,2035 r180 top
U6 "TPS7A3001DGNR" DGN0008D_N 695,1515 r90 top
U7 "TPS560200DBVR" DBV0005A_N 760,2030 r180 top
U8 "TPS79101DBVR" DBV0006A_N 1115,1860 r270 top
U10 "REF6030IDGKR" DGK0008A_N 1290,345 r180 top
U12 "OPA191IDBVR" DBV0005A_N 465,975 r270 top
U13 "THS4551IRGTR" RGT0016C 875,870 r0 top
U14 "ADS127L01IPBSR" PBS0032A_N 1360,840 r0 top
U15 "LMK00804BPW" PW0016A_N 1980,445 r0 top
U16 "SN74AUP1G80DCKR" DCK0005A_N 1985,155 r180 top
U17 "SN74AUP1G80DCKR" DCK0005A_N 2140,200 r180 top
U18 "OPA191IDBVR" DBV0005A_N 465,625 r270 top
U19 "TPS73118DBVR" DBV0005A_N 2142.69,2064 r0 top
Y1 "ASEMB-16.000MHZ-XY-T" ABRACON_ASEMB 1845,245 r90 top
ZZ1 "This Assembly Note is for PCB labels only" AssemblyNoteLabel -150,4500 r0 top
ZZ2 "These assemblies are ESD sensitive, ESD precautions shall be observed." AssemblyNote -150,4300 r0 top
ZZ3 "These assemblies must be clean and free from flux and all contaminants. Use of no clean flux is not acceptable." AssemblyNote -150,4100 r0 top
ZZ4 "These assemblies must comply with workmanship standards IPC-A-610 Class 2, unless otherwise specified." AssemblyNote -150,3900 r0 top

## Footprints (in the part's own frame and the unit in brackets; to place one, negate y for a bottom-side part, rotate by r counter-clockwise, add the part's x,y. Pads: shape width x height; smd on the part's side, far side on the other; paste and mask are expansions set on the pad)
0402 [mm] "0402 from SM-752 data"
  rect 0.8x0.6 smd: 1(-0.6,0) 2(0.6,0)
  silkscreen extent -1.22,-0.52 1.22,0.52, body extent -0.55,-0.3 0.55,0.3, height 0.6
0603 [mm] "0603 from SM-752 data"
  rect 1x0.95 smd: 1(-0.8,0) 2(0.8,0)
  silkscreen extent -1.52,-0.69 1.52,0.69, body extent -0.87,-0.47 0.87,0.47, height 1
0805_HV [mil] "0805 with 30mil clearance between pads"
  rect 50x63 smd: 1(-40,0) 2(40,0)
  silkscreen extent -74,-40 74,40, body extent -43,-29 43,29, height 57
1206_190 [mm] "1206_190"
  rect 1.1x1.6 smd: 1(-1.7,0) 2(1.7,0)
  silkscreen extent -0.9,-1 0.9,1, body extent -1.75,-0.95 1.75,0.95, height 1.9
ABRACON_ASEMB [mm] "ASEMB Series Oscillator"
  rect 1x0.9 smd: 1(-0.95,1.05) 2(-0.95,-1.05) 3(0.95,-1.05) 4(0.95,1.05)
  silkscreen extent -1.7,-1.75 1.7,1.75, body extent -1.25,-1.6 1.25,1.6, height 0.95
Amphenol_901-144-8RFX [mm] "SMA Straight Jack, TH"
  round 2 hole 1.5: 1(0,0)
  round 2.2 hole 1.7: 2(-2.54,2.54) 3(-2.54,-2.54) 4(2.54,-2.54) 5(2.54,2.54)
  silkscreen extent -3.7,-3.7 3.7,3.7, body extent -3.7,-3.7 3.7,3.7, height 9.93
AssemblyNote [mil] "Assembly Note"
AssemblyNoteLabel [mil] "Assembly Note for PCB Labels"
Bumpon_SJ61A2 [mil] "3M Hemispherical Bumpon transparent"
  round 1 on Mech4: 0(0,0)
  silkscreen extent -192,-192 192,192, body extent -193,-192 193,192, height 250
CPF0402 [mm] "TE Connectivity"
  rect 0.5x0.6 smd: 1(-0.5,0) 2(0.5,0)
  silkscreen extent -0.97,-0.53 0.97,0.53, body extent -0.55,-0.27 0.55,0.27, height 0.35
DBV0005A_N [mm] "SOT23, 5-Leads, Body 2.9x1.6mm, Pitch 0.95mm, Lead Span 2.8mm, IPC Medium Density"
  rrect17% 1x0.6 smd: 1(-1.375,0.95) 2(-1.375,0) 3(-1.375,-0.95) 4(1.375,-0.95) 5(1.375,0.95)
  silkscreen extent -1.63,-1.55 0.38,1.55, body extent -1.42,-1.46 1.42,1.46, height 1.09
DBV0006A_N [mm] "SOT23, 6-Leads, Body 2.9x1.6mm, Pitch 0.95mm, Lead Span 2.8mm, IPC Medium Density"
  rrect17% 1x0.6 smd: 1(-1.375,0.95) 2(-1.375,0) 3(-1.375,-0.95) 4(1.375,-0.95) 5(1.375,0) 6(1.375,0.95)
  silkscreen extent -1.68,-1.55 0.5,1.55, body extent -1.42,-1.46 1.42,1.46, height 1.12
DCK0005A_N [mm] "SOT353, 5-Leads, Body 2x1.3mm, Pitch 0.65mm, Lead Span 2.1mm, IPC Medium Density"
  rrect25% 0.85x0.4 smd: 1(-1.125,0.65) 2(-1.125,0) 3(-1.125,-0.65) 4(1.125,-0.65) 5(1.125,0.65)
  silkscreen extent -1.48,-1.02 0.55,1.1, body extent -1.14,-1 1.14,1, height 0.95
DDA0008E_N [mm]
  rrect17% 1.45x0.6 smd: 1(-2.725,1.905) 2(-2.725,0.635) 3(-2.725,-0.635) 4(-2.725,-1.905) 5(2.725,-1.905) 6(2.725,-0.635) 7(2.725,0.635) 8(2.725,1.905)
  rrect7% 2.95x4.9 smd paste-1.5 mask-1.5: 9(0,0)
  rrect4% 2.4x3.1 on Top Paste: 9(0,0)
  rrect4% 2.4x3.1 on Top Solder: 9(0,0)
  silkscreen extent -3.22,-2.5 1.4,2.5, body extent -3,-2.45 3,2.45, height 1.57
DGK0008A_N [mm] "TSOP, 8-Leads, Body 3x3mm, Pitch 0.65mm, IPC Medium Density"
  oval 1.35x0.45 smd: 1(-2.225,0.975) 2(-2.225,0.325) 3(-2.225,-0.325) 4(-2.225,-0.975) 5(2.225,-0.975) 6(2.225,-0.325) 7(2.225,0.325) 8(2.225,0.975)
  silkscreen extent -2.75,-1.55 0.95,1.55, body extent -2.45,-1.5 2.45,1.5, height 0.96
DGN0008D_N [mm] "TSOP, 8-Leads, Body 3x3mm, Pitch 0.65mm, Thermal Pad 1.89x1.57mm, IPC Medium Density"
  rrect100% 1.35x0.45 smd: 1(-2.225,0.975) 2(-2.225,0.325) 3(-2.225,-0.325) 4(-2.225,-0.975) 5(2.225,-0.975) 6(2.225,-0.325) 7(2.225,0.325) 8(2.225,0.975)
  rrect6% 1.57x1.89 smd: 9(0,0)
  silkscreen extent -2.73,-1.55 0.95,1.55, body extent -2.46,-1.5 2.46,1.5, height 1.1
FCC_disclaimer [mil]
Fiducial10-20 [mm]
  round 1 smd mask+0.5: 1(0,0)
  Top Layer keep-out circle w1.178: c0,0 r0.5
Harwin_S2751-46R [mm] "Test Point, SMT"
  rect 2.2x1.4 smd: 1(0,0)
  body extent -1,-0.6 1,0.6, height 1.4
Keystone_5019 [mm] "Test Point, Miniature, SMT"
  rect 3.8x2.03 smd: 1(0,0)
  silkscreen extent -2.31,-1.42 2.31,1.42, body extent -1.9,-1.02 1.9,1.02, height 2.29
Label_650x200 [mil] "Thermal Transfer Label"
  round 1 on Mech14: 0(0,0)
  silkscreen extent -325,-100 325,100, body extent -325,-100 325,100, height 1
Pb-Free_Overlay_Small [mil]
  silkscreen extent -46,-46 46,46
PBS0032A_N [mm]
  oval 1.4x0.3 smd: 1(-3.2,1.75) 2(-3.2,1.25) 3(-3.2,0.75) 4(-3.2,0.25) 5(-3.2,-0.25) 6(-3.2,-0.75) 7(-3.2,-1.25) 8(-3.2,-1.75) 17(3.2,-1.75) 18(3.2,-1.25) 19(3.2,-0.75) 20(3.2,-0.25) 21(3.2,0.25) 22(3.2,0.75) 23(3.2,1.25) 24(3.2,1.75)
  oval 0.3x1.4 smd: 9(-1.75,-3.2) 10(-1.25,-3.2) 11(-0.75,-3.2) 12(-0.25,-3.2) 13(0.25,-3.2) 14(0.75,-3.2) 15(1.25,-3.2) 16(1.75,-3.2) 25(1.75,3.2) 26(1.25,3.2) 27(0.75,3.2) 28(0.25,3.2) 29(-0.25,3.2) 30(-0.75,3.2) 31(-1.25,3.2) 32(-1.75,3.2)
  silkscreen extent -3.6,-2.53 2.53,2.53, body extent -3.51,-3.51 3.51,3.51, height 1.2
PW0016A_N [mm] "TSOP, 16-Leads, Body 5x4.4mm, Pitch 0.65mm, IPC Medium Density"
  oval 1.4x0.45 smd: 1(-2.95,2.275) 2(-2.95,1.625) 3(-2.95,0.975) 4(-2.95,0.325) 5(-2.95,-0.325) 6(-2.95,-0.975) 7(-2.95,-1.625) 8(-2.95,-2.275) 9(2.95,-2.275) 10(2.95,-1.625) 11(2.95,-0.975) 12(2.95,-0.325) 13(2.95,0.325) 14(2.95,0.975) 15(2.95,1.625) 16(2.95,2.275)
  silkscreen extent -3.5,-2.55 1.85,2.75, body extent -3.21,-2.5 3.21,2.5, height 1
RGT0016C [mm] "QFN, 16-Leads, Body 3x3mm, Pitch 0.5mm, Thermal Pad 1.7x1.7mm, TI Recommended"
  rrect42% 0.6x0.24 smd: 1(-1.4,0.75) 2(-1.4,0.25) 3(-1.4,-0.25) 4(-1.4,-0.75) 9(1.4,-0.75) 10(1.4,-0.25) 11(1.4,0.25) 12(1.4,0.75)
  rrect42% 0.24x0.6 smd: 5(-0.75,-1.4) 6(-0.25,-1.4) 7(0.25,-1.4) 8(0.75,-1.4) 13(0.75,1.4) 14(0.25,1.4) 15(-0.25,1.4) 16(-0.75,1.4)
  rrect6% 1.55x1.55 on Top Paste: 17(0,0)
  rrect6% 1.68x1.68 smd paste-0.85: 17(0,0)
  silkscreen extent -1.72,-1.73 1.72,1.73, body extent -1.5,-1.5 1.5,1.5, height 1
SOD-523 [mm] "NXP Semiconductor recommended land pattern, nominal STEP model"
  rect 0.8x0.6 smd paste-0.05: 1(-0.55,0) 2(0.55,0)
  silkscreen extent -1.65,-0.66 1.2,0.66, body extent -0.8,-0.4 0.8,0.4, height 0.72
SRN2010TA [mm] "SMD, 2-Leads, Body 2.0x1.6mm"
  rect 0.8x1.7 smd: 1(-0.75,0) 2(0.75,0)
  silkscreen extent -0.08,-0.9 0.08,0.9, body extent -1,-0.8 1,0.8, height 0.95
SRU2016 [mm] "BOURNS"
  round 0.5 smd: 1(-1.35,0.05) 2(1.35,-0.1)
  Top Layer region: 0.5,1.5 0.85,1.5 1.7,0.62 1.7,-0.62 0.85,-1.5 0.5,-1.5 0.5,-0.866 0.809,-0.588 0.978,-0.208 0.978,0.208 0.809,0.588 0.5,0.866 0.5,0.866
  Top Layer region: -0.5,-1.5 -0.85,-1.5 -1.7,-0.62 -1.7,0.62 -0.85,1.5 -0.5,1.5 -0.5,0.866 -0.809,0.588 -0.978,0.208 -0.978,-0.208 -0.809,-0.588 -0.5,-0.866 -0.5,-0.866
  silkscreen extent -0.25,-1.4 0.25,1.4, body extent -1.97,-1.97 1.97,1.97, height 1.65
Sullins_GRPB021VWVN-RC [mil] "Sullins"
  rrect10% 41x41 hole 28: 1(-25,0)
  round 41 hole 28: 2(25,0)
  silkscreen extent -70,-42 50,42, body extent -50,-42 50,42, height 157
Sullins_GRPB031VWVN-RC [mm] "SULLINS"
  oval 0.9x1.4 hole 0.7: 1(-1.27,0) 2(0,0) 3(1.27,0)
  silkscreen extent -2.25,-1.47 2.17,1.2, body extent -2.15,-1.17 2.17,1.17, height 4.2
Sullins_xPxC052LFBN [mm] "Receptacle, 2.54mm, 5x2, TH"
  rect 1.55x1.55 hole 1.02: 1(-5.08,1.27)
  round 1.55 hole 1.02: 2(-5.08,-1.27) 3(-2.54,1.27) 4(-2.54,-1.27) 5(0,1.27) 6(0,-1.27) 7(2.54,1.27) 8(2.54,-1.27) 9(5.08,1.27) 10(5.08,-1.27)
  silkscreen extent -6.6,-2.54 6.6,2.9, body extent -6.6,-2.54 6.6,2.54, height 8.5
TP_SM_1MM [mm] "1mm Test Point, SMT"
  round 1 smd paste-0.5: 1(0,0)
TSW-104-07-G-S [mm] "Samtec 100mil, 1x4, 230 mil above insulator"
  rrect6% 1.65x1.65 hole 1.016: 1(-3.81,0)
  round 1.65 hole 1.016: 2(-1.27,0) 3(1.27,0) 4(3.81,0)
  silkscreen extent -5.16,-1.27 5.08,1.65, body extent -5.08,-1.27 5.08,1.27, height 8.38
WL-SMCW_RED [mm] "WURTH"
  rect 0.8x0.8 smd: 1(-0.8,0) 2(0.8,0)
  silkscreen extent -1.9,-0.8 1.2,0.8, body extent -0.85,-0.45 0.85,0.45, height 0.8

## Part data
C1 C3 C4 C13 C14 C16 C17 C22 C24 C26 C28 C29: "CAP, CERM, 10 µF, 25 V, +/- 20%, X5R, 0603"
C2 C6 C9 C15 C27 C31 C89: "CAP, CERM, 0.1 µF, 25 V, +/- 10%, X5R, 0402"
C5 C20 C33: library part GRM155R71A393KA01D, "CAP, CERM, 0.039 µF, 10 V, +/- 10%, X7R, 0402"
C7 C10 C32 C90: "CAP, CERM, 1 µF, 25 V, +/- 10%, X5R, 0402"
C8 C11 C23 C25 C34 C57: "CAP, CERM, 0.01 µF, 50 V, +/- 10%, X5R, 0603"
C12: "CAP, CERM, 0.47 µF, 25 V, +/- 10%, X5R, 0603"
C18: "CAP, CERM, 91 pF, 50 V, +/- 5%, C0G/NP0, 0402"
C19: "CAP, CERM, 68 µF, 10 V, +/- 20%, X5R, 1206_190"
C21: "CAP, CERM, 2.2 µF, 25 V, +/- 10%, X5R, 0402"
C30: "CAP, CERM, 13 pF, 50 V, +/- 5%, C0G/NP0, 0402"
C46 C60 C64 C66 C68 C77 C79: "CAP, CERM, 10 µF, 10 V, +/- 20%, X5R, 0402"
C47: "CAP, CERM, 47 µF, 10 V, +/- 20%, X5R, 0805"
C50 C69 C70 C73 C74 C75 C80: "CAP, CERM, 1 µF, 10 V, +/- 10%, X5R, 0402"
C51: "CAP, CERM, 0.22 µF, 10 V, +/- 10%, X5R, 0402"
C52 C62: "CAP, CERM, 270 pF, 100 V, +/- 5%, C0G/NP0, 0603"
C53: "CAP, CERM, 470 pF, 100 V, +/- 5%, C0G/NP0, 0603"
C54: "CAP, CERM, 1000 pF, 100 V, +/- 5%, C0G/NP0, 0603"
C55: "CAP, CERM, 1600 pF, 100 V, +/- 5%, C0G/NP0, 0805"
C56 C59 C61 C63 C65 C67 C76 C78 C81 C82 C83 C84 C85 C86 C87: "CAP, CERM, 0.1 µF, 10 V, +/- 10%, X5R, 0402"
C71: "CAP, CERM, 10 pF, 50 V, +/- 5%, C0G/NP0, 0603"
C72: "CAP, CERM, 10 pF, 100 V, +/- 5%, C0G/NP0, 0603"
D1: "LED, Red, SMD"
D2: "Diode, Schottky, 100 V, 0.2 A, SOD-523"
FID1 FID2 FID3 FID4 FID5 FID6: "Fiducial mark.  There is nothing to buy or mount."
H1 H2: "Bumpon, Hemisphere, 0.375 X 0.235, Black"
J1 J2 J4 J5 J11 J12: "Header, 50mil, 2x1, Gold, TH"
J3: "Header, 50mil, 3x1, Gold, TH"
J7 J8: library part 901-144-8RFX, "SMA Straight Jack, Gold, 50 Ohm, TH"
J9: "Receptacle, 2.54mm, 5x2, Gold, TH"
J10: "Header, 100mil, 4x1, Gold, TH"
L1 L2 L4: "Inductor, Shielded, Ferrite, 10 µH, 0.45 A, 0.864 ohm, AEC-Q200 Grade 1, SMD"
L3: "Inductor, Drum Core, Ferrite, 22 µH, 0.37 A, 0.99 ohm, SMD"
L7: "Ferrite Bead, 600 ohm @ 100 MHz, 0.3 A, 0603"
LBL1: library part THT-14-423-10, "Thermal Transfer Printable Labels, 0.650\" W x 0.200\" H - 10,000 per roll"
Logo2: library part Pb-Free
Logo3: library part FCC_disclaimer, "FCC_disclaimer"
R1 R13 R19 R76: "RES, 0, 5%, 0.1 W, 0603"
R2 R57: "RES, 100 k, 1%, 0.063 W, 0402"
R3 R4 R6 R7 R12 R15 R23 R26 R42 R61 R70 R71 R72 R73 R74: library part CRCW04020000Z0ED, "RES, 0, 5%, 0.063 W, 0402"
R5: "RES, 30.9 k, 1%, 0.063 W, 0402"
R8: "RES, 75.0 k, 1%, 0.063 W, 0402"
R9: "RES, 105 k, 1%, 0.063 W, 0402"
R10 R17: library part RC0402FR-071KL, "RES, 1.00 k, 1%, 0.0625 W, 0402"
R11: "RES, 17.4 k, 1%, 0.063 W, 0402"
R14: "RES, 39.2 k, 1%, 0.063 W, 0402"
R16: "RES, 36 k, 5%, 0.063 W, 0402"
R18: "RES, 10.5 k, 1%, 0.063 W, 0402"
R20: "RES, 97.6 k, 1%, 0.1 W, AEC-Q200 Grade 0, 0402"
R22: "RES, 100 k, 1%, 0.0625 W, 0402"
R25: "RES, 30.1 k, 1%, 0.063 W, 0402"
R27: "RES, 17.8 k, 1%, 0.063 W, 0402"
R32: "RES, 0.22, 1%, 0.125 W, 0402"
R34 R49: "RES, 120 k, 1%, 0.063 W, 0402"
R35 R45: "RES, 1.00 k, 0.1%, 0.063 W, 0402"
R36 R40: "RES, 3.40 k, 1%, 0.063 W, 0402"
R37 R41: "RES, 330, 1%, 0.1 W, AEC-Q200 Grade 0, 0402"
R38 R43: "RES, 10.0, 0.1%, 0.063 W, 0402"
R39 R44: "RES, 4.99, 1%, 0.063 W, 0402"
R46 R62 R67: "RES, 100 k, 1%, 0.063 W, AEC-Q200 Grade 0, 0402"
R47: "RES, 10.0, 1%, 0.063 W, 0402"
R48 R51 R52 R54 R56 R58 R64: "RES, 0, 5%, 0.063 W, 0402"
R50 R53 R55 R59 R63 R68 R69: library part CRCW04021K00JNED, "RES, 1.0 k, 5%, 0.063 W, 0402"
R60: "RES, 10.0 k, 1%, 0.063 W, AEC-Q200 Grade 0, 0402"
R65 R66: "RES, 43.2, 1%, 0.063 W, 0402"
R75: "RES, 49.9 k, 0.1%, 0.063 W, 0402"
R78 R79 R80 R81 R82: library part CRCW06030000Z0EA, "RES, 0, 5%, 0.1 W, 0603"
TP1 TP2 TP5 TP6 TP7 TP9 TP10 TP11 TP17: library part TP_SM_1MM, "1mm Test Point, SMT"
TP3 TP4: library part 5019, "Test Point, Miniature, SMT"
TP8 TP13 TP14 TP15 TP16 TP18 TP19: library part S2751-46R, "Test Point, SMT"
U1 U5 U7: "17V Input, 500mA Synchronous Step-Down Regulator in SOT-23 with Advanced Eco-Mode(TM), DBV0005A (SOT-5)"
U2 U3: "Single Output High PSRR LDO, 100 mA, Fixed 3.3 V Output, 2.7 to 5.5 V Input, 5-pin SOT-23 (DBV), -40 to 125 degC, Green (RoHS & no Sb/Br)"
U4: "SIMPLE SWITCHER, 36V 1A Synchronous Step-Down Converter, DDA0008E (SOIC-8)"
U6: "Single Output High PSRR LDO, 200 mA, Adjustable -1.18 to -33 V Output, -3 to -36 V Input, with Ultra-Low Noise, 8-pin MSOP (DGN), -40 to 125 degC, Green (RoHS & no Sb/Br)"
U8: "Single Output High PSRR LDO, 100 mA, Adjustable 1.2 to 5.5 V Output, 2.7 to 5.5 V Input, 6-pin SOT-23 (DBV), -40 to 125 degC, Green (RoHS & no Sb/Br)"
U10: "High-Precision Voltage Reference with Integrated High-Bandwidth Buffer, DGK0008A (VSSOP-8)"
U12 U18: "36-V, Low Power, Precision, CMOS, Rail-to-Rail Input/Output, Low Offset Voltage, Low Input Bias Current Op Amp, DBV0005A (SOT-5)"
U13: "Low Noise, Precision, 150MHz, Fully Differential Amplifier, RGT0016C (VQFN-16)"
U14: "24-Bit, 512kSPS, Delta-Sigma ADC, PBS0032A (TQFP-32)"
U15: "Low Skew, 1-to-4 Multiplexed Differential/LVCMOS-to-LVCMOS/TTL Fanout Buffer, PW0016A"
U16 U17: "LOW-POWER SINGLE POSITIVE-EDGE-TRIGGERED D-TYPE FLIP-FLOP, DCK0005A"
U19: "Single Output Fast Transient Response LDO, 150 mA, Fixed 1.8 V Output, 1.7 to 5.5 V Input, 5-pin SOT-23 (DBV), -40 to 85 degC, Green (RoHS & no Sb/Br)"
Y1: "Oscillators, 16MHz, CMOS, 1.8 to 3.3V, SMD"
ZZ1: library part AssemblyNoteLabel
ZZ2 ZZ3 ZZ4: library part AssemblyNote

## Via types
v1: diameter 20, hole 10, Top Layer to Bottom Layer, tented top, 130 vias
v2: diameter 20, hole 10, Top Layer to Bottom Layer, 85 vias
v3: diameter 20, hole 10, Top Layer to Bottom Layer, tented both sides, 20 vias
v4: diameter 19.68, hole 7.87, Top Layer to Bottom Layer, 14 vias
v5: diameter 20, hole 10, Top Layer to Bottom Layer, tented bottom, 12 vias
v6: diameter 30, hole 15, Top Layer to Bottom Layer, tented top, 8 vias
v7: diameter 19.68, hole 7.87, Top Layer to Bottom Layer, tented both sides, 4 vias
v8: diameter 30, hole 15, Top Layer to Bottom Layer, 1 vias
v9: diameter 30, hole 15, Top Layer to Bottom Layer, tented both sides, 1 vias

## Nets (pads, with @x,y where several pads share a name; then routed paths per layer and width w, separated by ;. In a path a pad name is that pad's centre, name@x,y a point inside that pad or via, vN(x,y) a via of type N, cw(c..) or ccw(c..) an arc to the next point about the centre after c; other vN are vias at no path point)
3.3V: C46.1 J1.2 U10.1 U10.2 | length 2993.2
  Top Layer w15: U10.2@1377.6,331.06 U10.2@1377.6,332.2
  Top Layer w50: v8(760,315) 760,195 825,130 1025,130 1065,170 1380,170 1380,304.21 U10.1@1377.6,306.61
  Layer 3 - PWR w41: J1.2@1330,1345 1330,1405
  Layer 3 - PWR w50: v8@765,315 v8(760,315) 705,370 705,1280 915,1490 1010,1490 1145,1625 1337.87,1625 1337.87,1389.8
  Bottom Layer w20: J1.2@1330,1337.79 J1.2@1330,1345
3V_REF: C47.1 C75.1 C76.2 U10.5 U10.6 U14.9 | length 600.6
  Top Layer w10: U10.6@1202.4,357.8 1244.8,357.8
  Top Layer w15: C47.1@1110,385 1110,445 ; C47.1@1111.62,383.39 U10.5@1202.4,383.39 U10.6@1202.4,357.8
  Top Layer w20: C47.1@1108.22,385 C47.1@1110,385
  Top Layer w25: 1244.8,357.8 1244.8,481.84 1254.38,491.42 C75.1@1254.38,570 1252.5,570 1224.38,598.12 C76.2@1224.38,620 1224.38,641.06 1274.31,691 1283,691
5.2V: C56.2 C86.2 J5.2 U12.5 U18.5 | length 1455.8
  Top Layer w15: C56.2@493.62,520 502.4,528.78 U18.5@502.4,570.87 ; C56.2@498.62,520 v6(545,520) ; U12.5@502.4,920.87 502.4,891.65 ; C86.2@503.62,865 502.4,866.22 502.4,891.65 ; v6@543.35,891.65 502.4,891.65
  Layer 3 - PWR w41: 910,1570 J5.2@930,1590
  Layer 3 - PWR w50: v6(545,520) v6(545,891.65) 545,1253 862,1570 910,1570
12V_SOURCE: C1.1 C2.1 C13.1 C14.1 C15.1 C26.1 C27.1 R7.1 R75.2 TP3.1 U1.4 U4.7 U5.4 U7.4 | length 786.4
  Top Layer w15: C1.1@1488.62,2027.13 C2.1@1488.62,2095 ; U1.4@1492.4,1969.13 1492.4,2010.91 C1.1@1508.62,2027.13
  Top Layer w20: C27.1@585,2083.62 597.87,2096.5 C26.1@645,2096.5 670.43,2071.06 674.77,2071.06 674.77,2067.4 U7.4@705.87,2067.4
  Top Layer w23: R75.2@263.62,2180 355,2180 v2(365,2170) ; C13.1@341.5,2005 R7.1@406.38,2005 ; U4.7@360,1932.28 C13.1@360,2000
  Top Layer w40: C2.1@1488.62,2095 C2.1@1492.56,2095 ; 1512.56,2095 1539.06,2121.5 C14.1@1690,2121.5 ; C14.1@1675,2121.5 1699.74,2121.5 U5.4@1740.87,2080.37
  other v1: 685,2090 685,2120 685,2150
  other v2: 720,2090 1545,2090 1575,2090 720,2120 1545,2121.5 1575,2121.5 365,2140 395,2140 720,2150 1545,2150 1575,2150 395,2170 365,2200 395,2200
-5.2V: C61.2 C87.2 J4.2 U12.2 U18.2 | length 612.3
  Top Layer w15: v1(463.62,768.62) C61.2@463.62,730 465,728.62 U18.2@465,679.13 ; U12.2@465,1029.13 465,1050
  Top Layer w20: 465,1050 v2(465,1120)
  Top Layer w41: v2(465,1120) J4.2@465,1200
  Layer 3 - PWR w50: v1(463.62,768.62) v2@463.62,1120
\CS: J9.1 R46.2 TP8.1 U14.23 | length 961.6
  Top Layer w9: U14.23@1485.98,889.21 1533.41,889.21 1538.69,883.93 1723.93,883.93 v5(1740,900)
  Top Layer w15: v5(1740,900) 1740,1001.28 1878.72,1140 TP8.1@2150,1140
  Top Layer w20: TP8.1@2150,1140 J9.1@2280,1140
\DRDY: J9.9 TP16.1 U14.19 | length 907
  Top Layer w9: U14.19@1485.98,810.47 v2@1540,810.47
  Top Layer w15: v2(1540,805) 1550,805 1565.37,789.63 1565.37,734.63 1625,675 2065,675 2130,740 TP16.1@2150,740 J9.9@2280,740
ADC_3.3V: C63.2 C64.1 C65.2 C66.1 J12.2 U14.6 U14.32 | length 1436.5
  Top Layer w10: 1153.36,768.34 1160.99,775.97 ; 1159.5,774.49 1195.49,810.47 U14.6@1234.02,810.47 U14.6@1249.02,810.47 ; 1285.47,810.47 1291.1,816.1 U14.32@1291.1,965.98
  Top Layer w11: U14.6@1249.02,810.47 1285.47,810.47
  Top Layer w25: C66.1@1143.62,715 C65.2@1143.62,755
  Top Layer w35: J12.2@1125,1270 1125,1100 1140,1085 C64.1@1251.38,1085 C63.2@1251.38,1035 1251.38,963.62
  Layer 3 - PWR w80: J12.2@1125,1250.53 1125,1105 1109.68,1089.68 1054.68,1089.68 1052.13,1087.13 1052.13,887.87 1185,755 1185,705
  other v1: 1160,715 1160,755
ADC_4MHZ: R70.2 U16.1 U16.4 | length 385
  Top Layer w15: v2(1922,210) 1940.71,191.29 U16.4@1940.71,180.59 1944.41,180.59 1995.59,129.41 U16.1@2029.29,129.41
  Bottom Layer w15: R70.2@1733.62,330 1802,330 v2(1922,210)
ADC_8MHZ: R69.2 U16.2 U17.1 U17.4 | length 656.9
  Top Layer w15: U16.2@2029.29,155 2005,155 1995,165 1995,205 2015.59,225.59 v1(2025,225.59) U17.4@2095.71,225.59 2099.41,225.59 2150.59,174.41 U17.1@2184.29,174.41
  Bottom Layer w15: R69.2@1733.62,390 1785,390 1949.41,225.59 v1(2025,225.59)
ADC_16MHZ: R66.2 R68.2 U17.2 | length 606.9
  Top Layer w15: R66.2@1986.38,300 1986.38,297.94 v1(2024.32,260) 2106.49,260 2127.81,238.68 2127.81,236.87 2164.69,200 U17.2@2184.29,200
  Bottom Layer w15: R68.2@1733.62,440 1785,440 1965,260 v1(2024.32,260)
ADS127L01_DIGITAL_CLK: R47.2 R68.1 R69.1 R70.1 | length 736.2
  Top Layer w15: R47.2@1608.62,975 R47.2@1610,976.38
  Top Layer w20: R47.2@1610,976.38 v1(1610,990)
  Bottom Layer w15: v1(1610,990) 1575,955 1575,770 1650,695 1650,476.38 R68.1@1686.38,440 R70.1@1686.38,330
AGND: C1.2 C2.2 C3.2 C4.2 C6.2 C7.2 C8.2 C9.2 C10.2 C11.2 C14.2 C15.2 C16.2 C17.2 C18.1 C19.1 C22.2 C24.2 C25.2 C26.2 C27.2 C28.2 C29.2 C31.2 C32.2 C34.2 C46.2 C50.2 C51.2 C56.1 C57.2 C59.2 C60.1 C61.1 C63.1 C64.2 C65.1 C66.2 C70.1 C73.2 C74.2 C75.2 C76.1 C86.1 C87.1 C89.2 C90.2 D1.1 D2.1 J7.2 J7.3 J7.4 J7.5 J8.2 J8.3 J8.4 J8.5 L3.2 R3.2 R4.2 R5.1 R6.2 R8.2 R12.2 R14.1 R17.1 R18.1 R23.2 R25.1 R26.2 R27.1 R32.1 R34.1 R42.2 R49.1 R61.2 R71.2 R72.2 R73.2 R74.2 R78.1 R78.2 R79.1 R79.2 R80.1 R80.2 R81.1 R81.2 R82.1 R82.2 TP4.1 TP19.1 U1.2 U2.2 U3.2 U5.2 U6.4 U6.9 U7.2 U8.2 U10.7 U10.8 U13.13 U13.14 U13.15 U13.16 U13.17@875,870 U14.5 U14.10 U14.31 U19.2 | length 5644.9
  Top Layer w10: U13.16@845.47,925.12 U13.15@865.16,925.12 ; 857.68,1022.2 857.68,972.2 857.68,950.33 865,943 865,925.28 U13.15@865.16,925.12 ; C60.1@893.62,710 C59.2@893.62,760 ; U13.13@904.53,925.12 U13.14@884.84,925.12 U13.15@865.16,925.12 ; C66.2@1096.38,705 C65.1@1096.38,755 1096.38,773.5 1110,787.13 1146.86,787.13 1189.9,830.16 U14.5@1234.02,830.16 U14.5@1249.02,830.16 ; C73.2@1096.38,970 C70.1@1096.38,1020 ; v3@1298.62,1070 C64.2@1298.62,1085 v3(1298.62,1100.69) ; 1303.47,660.47 1309.41,666.41 1309.41,684.11 1310.79,685.49 U14.10@1310.79,714.02
  Top Layer w11: C63.1@1298.62,1035 1310.79,1022.83 U14.31@1310.79,965.98
  Top Layer w15: v1(90,2145) 90,2176.5 D1.1@93.5,2180 ; v3(410,870) C86.1@451.38,870 ; C22.2@585,1563.5 C24.2@585,1496.5 U6.9@670.59,1496.5 ; v4(718.62,1497.28) 733.39,1482.52 U6.4@733.39,1427.4 733.39,1357.01 R18.1@730,1353.62 ; v4(718.62,1532.72) 757.22,1532.72 R17.1@790,1565.5 ; C25.2@771.5,1670 794.63,1646.87 794.63,1566.75 R17.1@796.38,1565 ; R26.2@868.62,1930 868.62,2000.12 C28.2@878.5,2010 ; U10.7@1202.4,332.2 1202.4,246.22 R32.1@1213.62,235 C46.2@1326.38,235 C50.2@1326.38,450 1330,453.62 1330,485 1415,485 1455,445 R34.1@1455,403.62 ; C6.2@1215,1571.38 C6.2@1221.38,1565 ; 1301.62,620 1301.62,658.62 1303.47,660.47 ; 1371.38,1912.26 1375.5,1916.38 ; C2.2@1433.5,2087.13 C2.2@1441.38,2095 ; v2(1453.5,1918.5) 1453.5,1936.41 ; R6.2@1585,1478.62 C9.2@1585,1541.38 1591.38,1535 U3.2@1640.87,1535 1670,1535 ; v1(1615,2056.38) 1674.82,2056.38 1686.2,2045 1740,2045 1750,2035 v2@1790,2035 ; v1@1683.37,1445 1683.37,1521.63 1670,1535 ; C10.2@1805,1521.38 1791.38,1535 1670,1535 ; R12.2@1851.38,1935 R14.1@1788.62,1935 1788.62,2033.62 v2@1790,2035 ; 1913.5,2032.73 1911.24,2035 U5.2@1849.13,2035 v2@1790,2035
  Top Layer w20: C18.1@465,1563.54 512.16,1563.54 R8.2@515,1566.38 ; C27.2@585,2036.38 642.13,2036.38 C26.2@645,2033.5 648.5,2030 v2(765,2030) ; R27.1@758.62,1930 758.62,2023.62 v2(765,2030) ; 878.5,2037.2 871.3,2030 U7.2@814.13,2030 v2(765,2030) ; 966.5,1846.5 C34.2@1000,1846.5 1000,1901.38 R23.2@1010,1911.38 ; C31.2@1111.38,1975 C31.2@1115,1971.38 ; R3.2@1215,1508.62 C6.2@1215,1571.38 ; C6.2@1221.38,1565 U2.2@1270.87,1565 1305,1565 ; C63.1@1298.62,1035 v3@1298.62,1070 ; 1301.62,599.5 1301.62,620 ; C8.2@1313.5,1455 1313.5,1556.5 1305,1565 ; R5.1@1355,1916.38 1375.5,1916.38 1451.38,1916.38 v2(1453.5,1918.5) ; R4.2@1368.62,2035 v1(1415,2035) ; C2.2@1433.5,2087.13 C1.2@1433.5,2035 1447.32,2021.18 1447.32,1942.6 1453.5,1936.41 1455,1934.92 U1.2@1455,1860.87 1455,1815 1485,1785 1533.5,1785 C4.2@1538.5,1790 C3.2@1538.5,1725 ; C7.2@1435,1541.38 1428.62,1541.38 1405,1565 1305,1565 ; C17.2@1913.5,2000 1913.5,2032.73 C16.2@1913.5,2060 ; C57.2@2118.5,1955 2118.5,1984.43 2140,2005.93 v2@2140,2055 ; v2@2131,2064 v2@2140,2055 ; C90.2@2250,2118.62 2233.62,2135 2195,2135 2190,2140 2164.98,2140 2140,2115.02 v2@2140,2055
  Top Layer w23: 966.5,1846.5 950,1830 950,1730 960,1720 R25.1@996.38,1720 ; C34.2@1000,1846.5 1119.25,1846.5 ; v2@1115,1850.75 U8.2@1115,1914.13 C31.2@1115,1971.38 ; v2(1115,1858.62) C32.2@1215,1858.62
  Top Layer w24: 878.5,2037.2 C29.2@878.5,2075
  Top Layer w25: C75.2@1301.62,570 1301.62,599.5 ; v3@1327.21,574.79 v3(1329,573) 1329.38,573.38 C74.2@1360,573.38
  Layer 2 -GND w40: 1209,1092 1209,1222.27
  other v1: 1230,235 1310,235 430,520 1005,655 903,698 1075,705 924,718 1075,755 1110,965 1805,1025 1855,1025 1905,1025 1955,1025 2005,1025 1110,1031.81 395,1080 595,1095 655,1095 890,1095 595,1195 655,1195 885,1195 1025,1195 1685,1445 1295,1455 1585,1495 1805,1505 1215,1525 1435,1525 1585,1525 1620,1535 465,1544.27 515,1545 1215,1555 1245,1565 150,1600 975,1720 1520,1725 1520,1785 900,1825 575,1850 650,1850 980,1850 1925,1850 1975,1850 1230,1860 1115,1895 575,1900 650,1900 1355,1900 890,1935 1805,1935 1835,1935 575,1950 650,1950 2095,1955 1620,1970 1660,1970 1700,1970 1115,1990 1895,2000 855,2005 645,2015 585,2020 1835,2035 2035,2035 1675,2040 1895,2060 100,2075 150,2075 200,2075 250,2075 450,2075 480,2075 510,2075 540,2075 2400,2100 450,2105 540,2105 2250,2135 2310,2175 2400,2200
  other v2: 1480,155 1480,245 150,1475 200,1475 250,1475 300,1475 350,1475 420,1480 455,1480 110,1510 150,1550 100,1575 300,1600 100,1625 100,1675 260,1770 800,1775 900,1775 90,1845 130,1845 1150,1858.62 1080,1860 2000,1950 90,1980 600,1985 650,1985 1305,1990 1795,1995 750,2000 1620,2005 1660,2005 1700,2005 90,2010 2140,2025 1795,2035 2140,2060 1795,2075 2140,2100 480,2105 510,2105 125,2125 175,2125 225,2125 275,2125 2400,2150 2270,2175 1625,2200 1675,2200 1725,2200 1775,2200 1825,2200 1875,2200 1800,2215 1850,2215
  other v3: 1455,420 1310,435 1075,580 1327.21,604 395,730 1298.62,1073 1385,2000
  other v4: 851.77,846.77 888.23,846.77 875,870 851.77,893.23 888.23,893.23 671.38,1497.28 695,1515 671.38,1532.72
  other v5: 1455,1845
  other v6: 835,975 835,1025
AINN: C55.1 R38.2 U14.3 | length 227
  Top Layer w10: R38.2@1035,910.32 1104.68,910.32 C55.1@1110,905 ; C55.1@1112.8,902.2 1152.8,902.2 1185.47,869.53 U14.3@1234.02,869.53 U14.3@1249.02,869.53
AINP: C55.2 R43.2 U14.4 | length 225.6
  Top Layer w10: R43.2@1035,829.68 1103.11,829.68 C55.2@1108.9,823.9 ; C55.2@1110,825 1156.97,825 1181.81,849.84 U14.4@1234.02,849.84 U14.4@1249.02,849.84
D1.8V: C67.2 C68.1 C79.1 C83.1 C84.1 J3.2 J10.2 J10.3 L7.1 R46.1 R50.2 R53.2 R55.2 R57.2 R58.2 R62.2 R63.2 U14.27 U16.5 U17.5 | length 3035.9
  Top Layer w10: C67.2@1386.38,1035 C67.2@1389.53,1031.85 ; C68.1@1386.38,1085 C68.1@1389.53,1081.85
  Top Layer w11: U14.27@1389.53,965.98 C67.2@1389.53,1031.85
  Top Layer w15: v1(1880,155) C83.1@1880,138.62 1889.21,129.41 U16.5@1940.71,129.41 ; U17.5@2095.71,174.41 2110.59,174.41 2123.38,161.62 C84.1@2123.38,115
  Top Layer w20: C84.1@2121.38,115 C84.1@2123.38,113 ; C84.1@2123.38,115 C84.1@2123.38,113 ; J10.3@2390,280 2390,268 2286,164 2286,163.63 2207.37,85 2145.79,85 2123.38,107.41 C84.1@2123.38,113
  Top Layer w25: L7.1@2280,317.5 2280,376.38 C79.1@2286,382.38 ; C79.1@2288.38,380 J10.2@2390,380
  Top Layer w30: C67.2@1386.38,1035 C68.1@1386.38,1085
  Layer 3 - PWR w30: v3(1130,520) 1508,520 v5(1509,521) 1577,521 ; 1592.38,525 1581,525 1577,521 ; 1596.38,525 1592.38,521 1577,521
  Layer 3 - PWR w40: v1(1375,1045) 1605,1045 1605,1181.28 1615,1191.28
  Layer 3 - PWR w41: 1360,1191.28 1615,1191.28 2141.28,1191.28 2337.87,1387.87 2337.87,1467.87 ; 2221,1983 2250.09,2012.09 ; 2250.09,2042.09 J3.2@2355,2042
  Bottom Layer w10: v5(1509,521) R50.2@1509,541.38
  Bottom Layer w20: R62.2@1626.38,780 1640,793.62 v1(1640,810)
  other v1: 2105,115
  other v3: 1212,522
  other v5: 1411,521 1675,910 1360,1210 1410,1210
D3.3V: C77.1 C78.2 C85.2 J2.2 R67.2 U15.3 Y1.4 | length 1224.7
  Top Layer w15: R67.2@1730,233.62 1730,286.38 1733.62,290 Y1.4@1796.06,290 ; C85.2@1730,291.38 1693.62,291.38 1690,295 1690,465 v6(1705,480) 1706.38,481.38 C77.1@1745,481.38 ; C77.1@1747.01,483.39 U15.3@1863.86,483.39
  Layer 3 - PWR w30: v6(1705,480) 1790,480 1839.61,529.61 1839.61,853.9 1710,983.51 J2.2@1710,1035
